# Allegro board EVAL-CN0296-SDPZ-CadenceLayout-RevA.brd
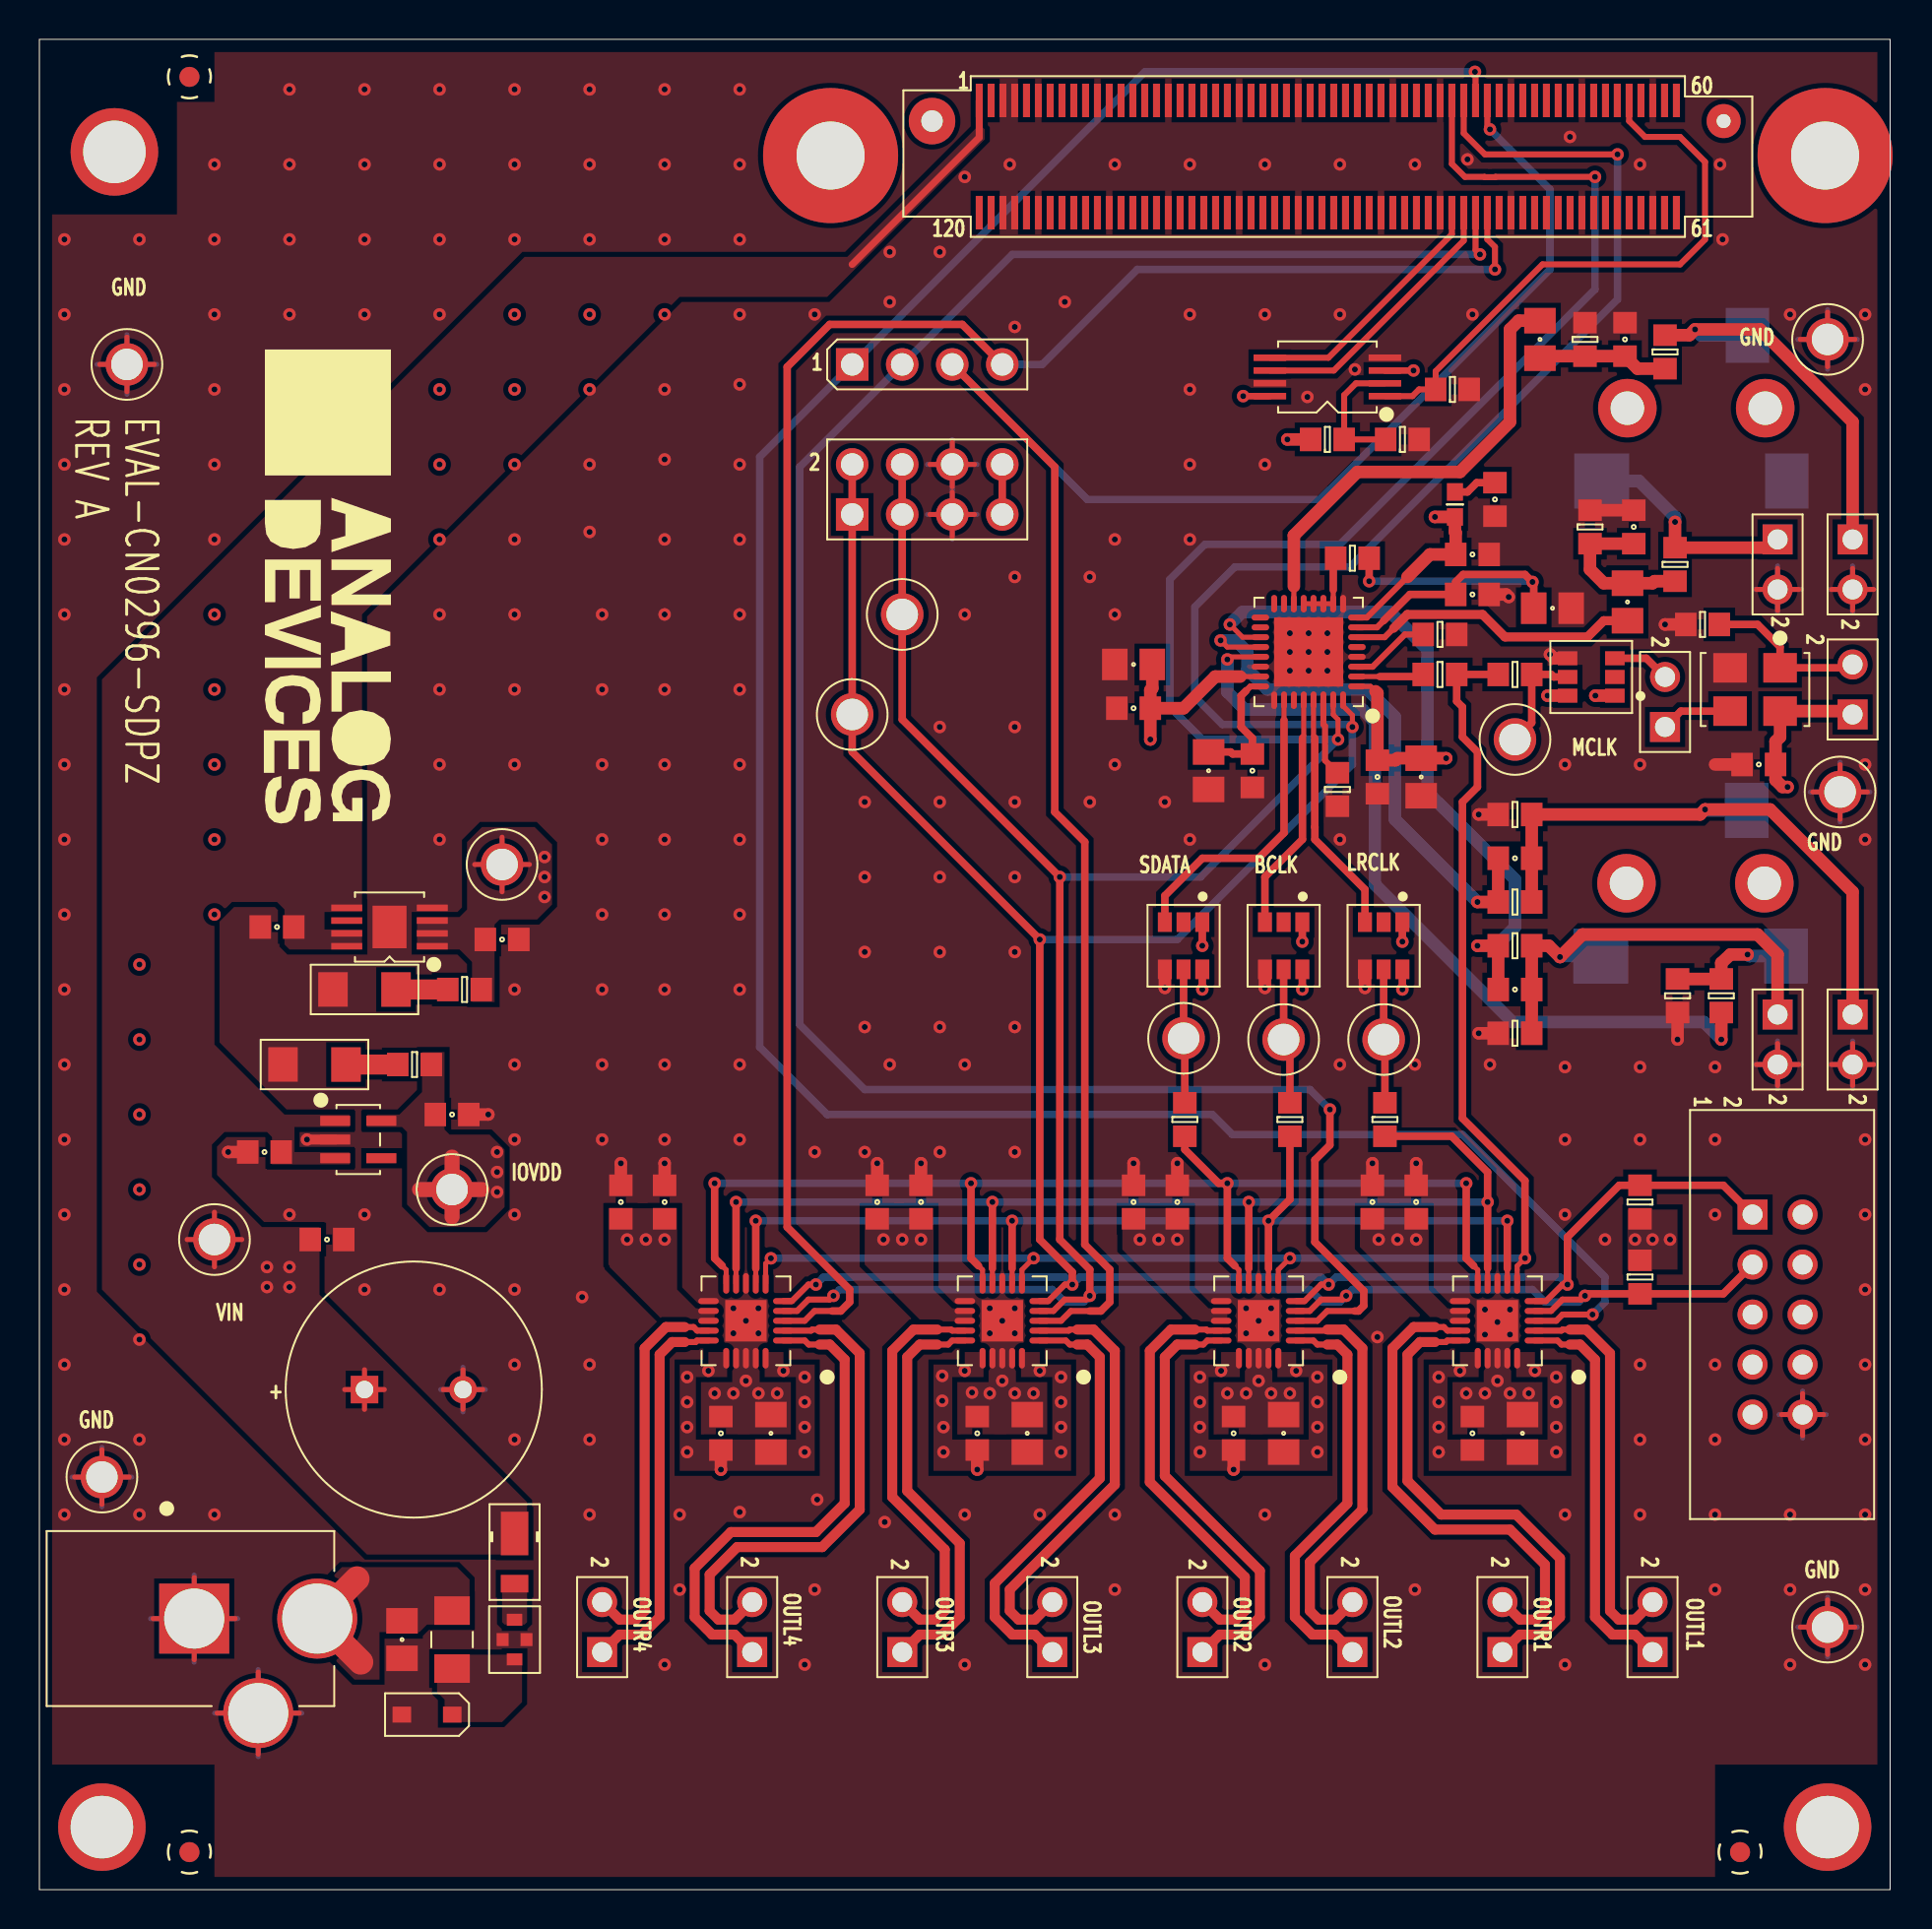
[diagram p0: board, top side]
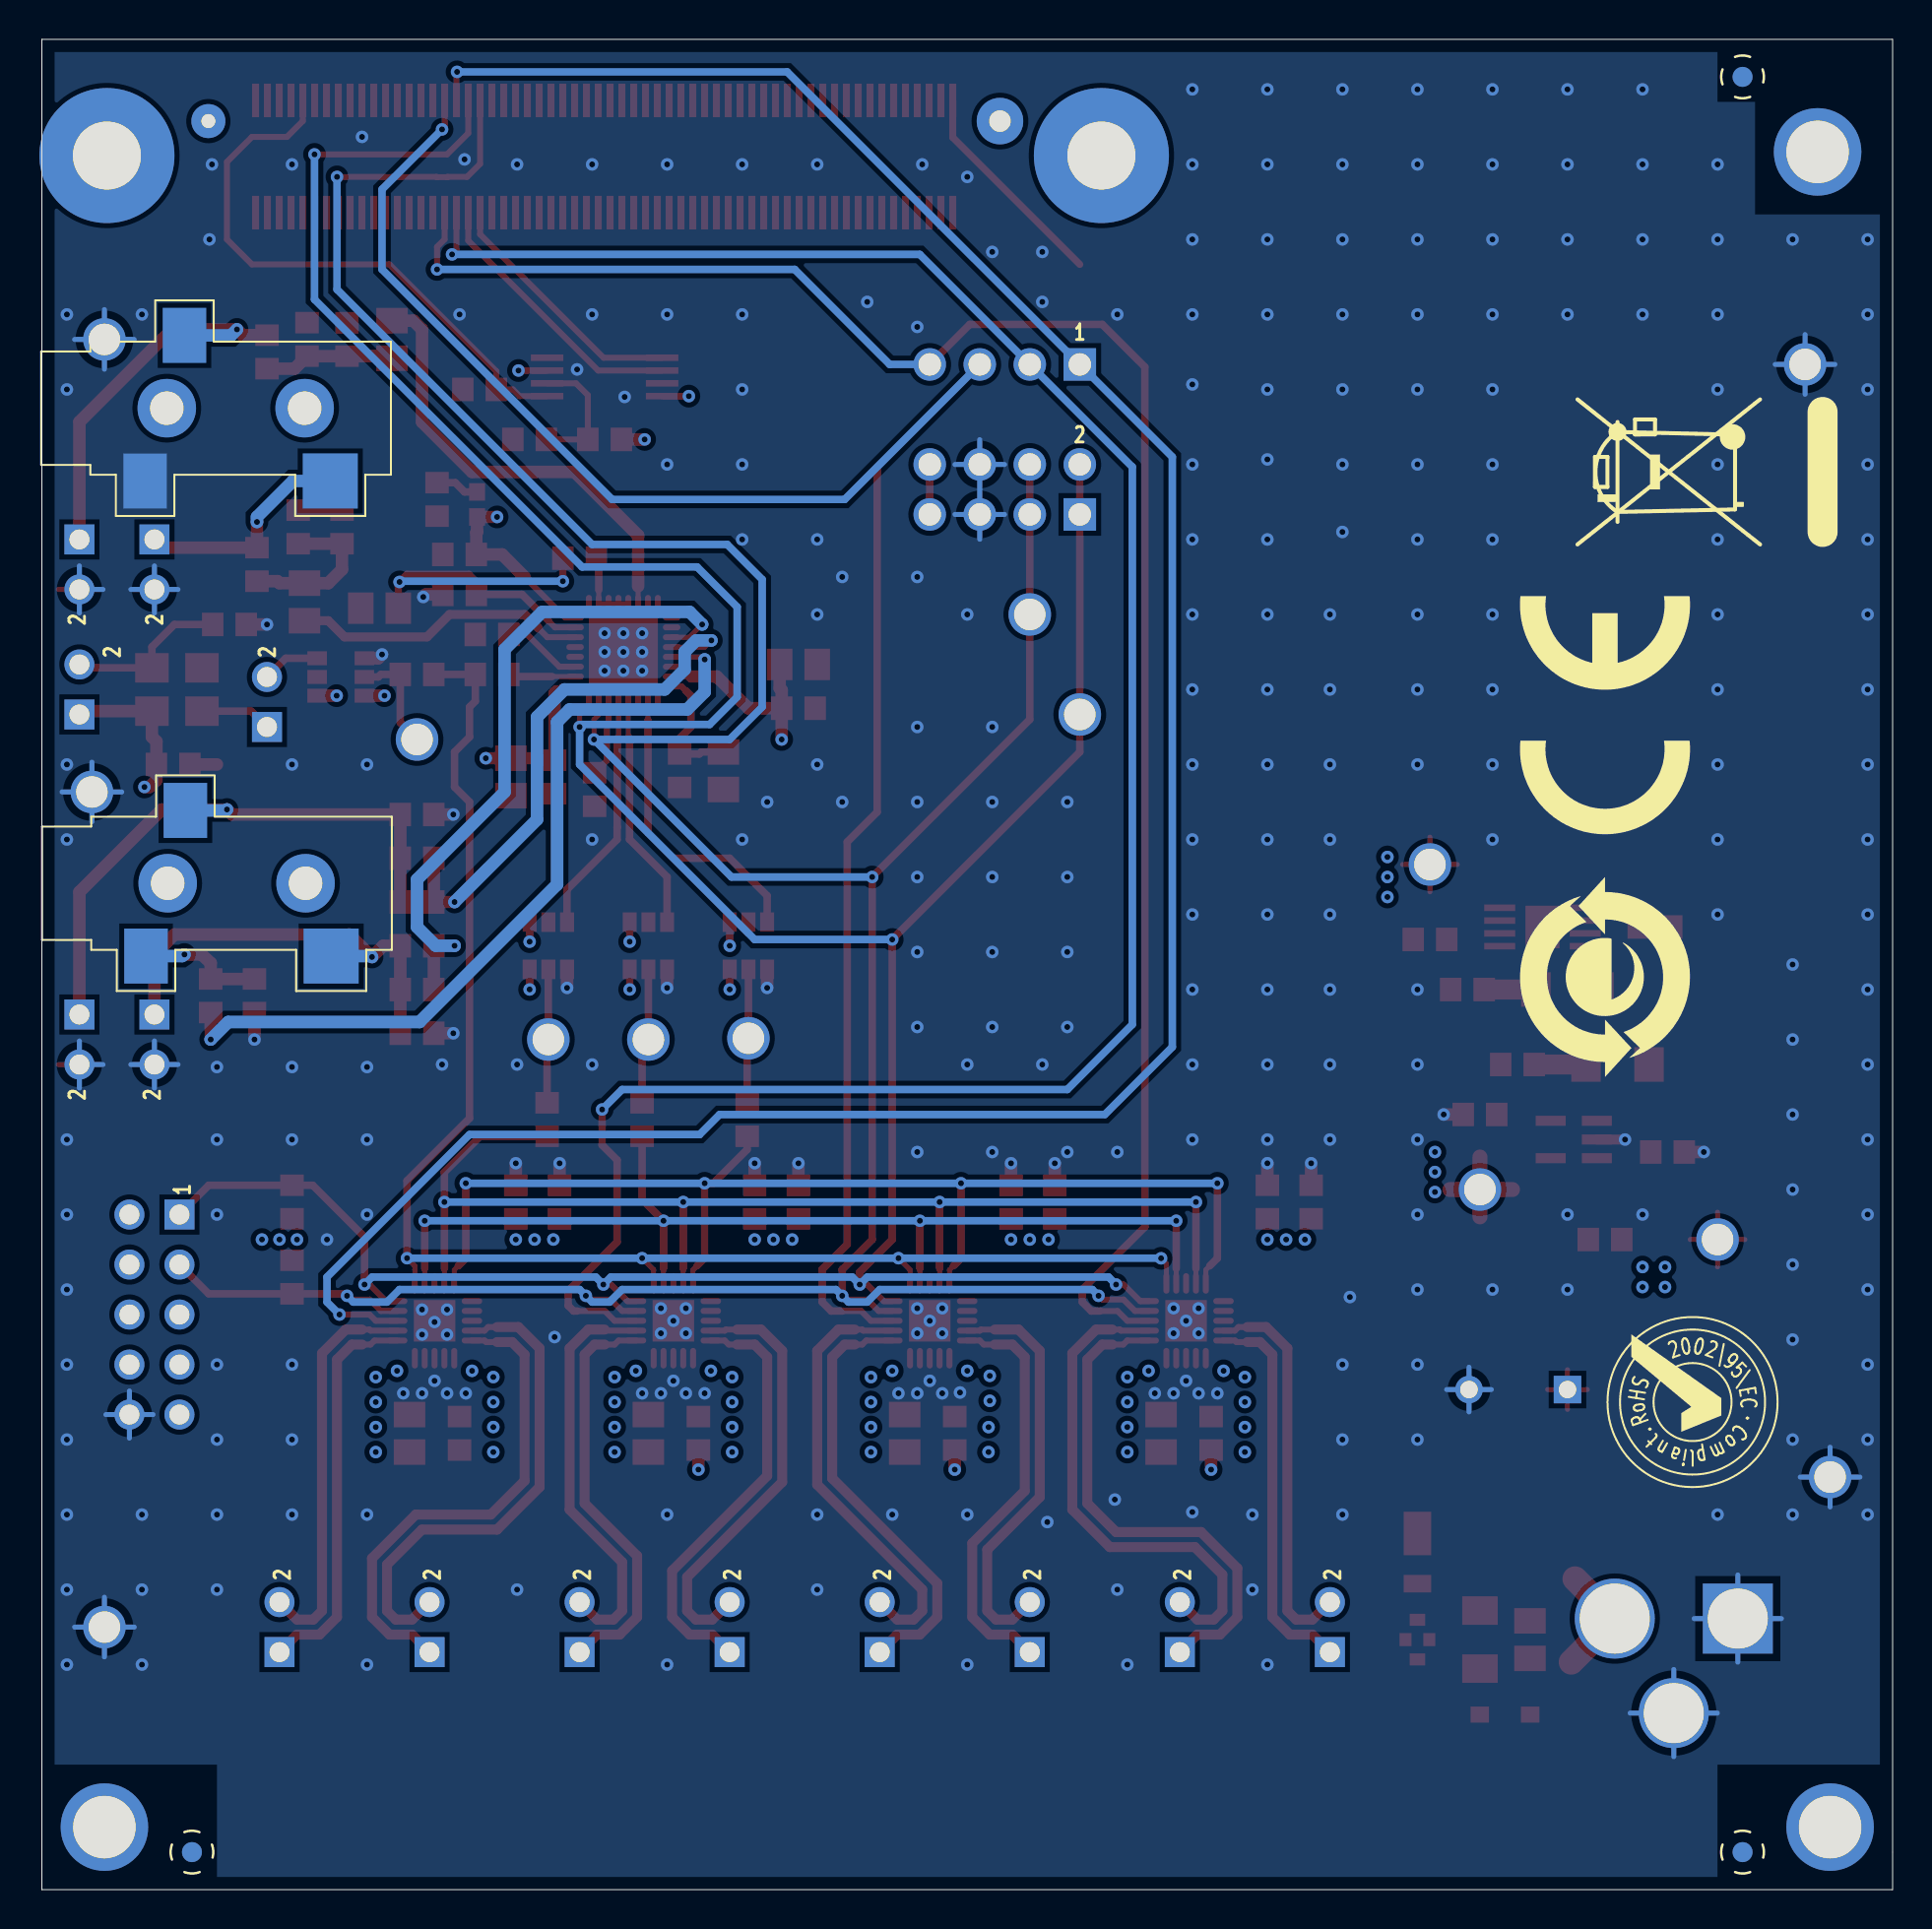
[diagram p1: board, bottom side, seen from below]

Outline 93.98 x 93.98 mm; copper layers: TOP, L2_DGND, L3_PWR, BOTTOM. Coordinates in mm from the lower left corner of the outline.
Outline path: 0,93.98 0,0 93.98,0 93.98,93.98 0,93.98

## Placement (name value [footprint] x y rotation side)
C1  1UF  [C0603]  11.43 37.47 180 top
C2  1.5uF  [C0603]  20.96 39.37 0 top
C3  4.7UF  [C0805]  18.41 12.7 270 top
C4  0.1uF  [C0603]  14.61 33.02 0 top
C5  1UF  [C0603]  12.07 48.9 180 top
C6  1.5uF  [C0603]  23.5 48.26 0 top
C7  1UF  [C0603]  29.53 34.93 90 top
C8  470uF  [CPLRAD197D492H866LD24]  16.51 25.4 0 top
C9  10UF  [C0603]  31.75 34.93 90 top
C10  0.1UF  [C0603]  34.61 23.18 270 top
C11  10UF  [C0805]  37.15 23.18 90 top
C12  10UF  [C0805]  55.56 62.23 0 top
C13  0.1uF  [C0603]  55.56 60.01 0 top
C14  0.1uF  [C0603]  72.77 67.82 180 top
C15  9.1pF  [C0603]  73.91 70.61 90 top
C16  10UF  [C0805]  59.37 56.83 270 top
C17  0.1uF  [C0603]  61.59 56.83 270 top
C18  10UF  [C0805]  70.17 56.52 270 top
C19  0.1uF  [C0603]  67.95 56.52 270 top
C20  10UF  [C0805]  76.84 65.09 0 top
C21  0.1uF  [C0603]  72.77 65.79 180 top
C22  10UF  [C0805]  80.65 65.41 270 top
C23  TBD0603  [C0603]  80.96 69.22 270 top
C24  10UF  [C0805]  76.2 78.74 90 top
C25  TBD0603  [C0603]  80.52 78.74 270 top
C26  TBD0603  [C0603]  74.93 52.39 180 top
C27  TBD0603  [C0603]  74.93 45.72 180 top
C28  0.01UF  [C0603]  87.31 57.15 180 top
C29  1UF  [C0603]  67.69 34.93 90 top
C30  10UF  [C0603]  69.91 34.93 90 top
C31  0.1UF  [C0603]  72.77 23.18 270 top
C32  10UF  [C0805]  75.31 23.18 90 top
C33  1UF  [C0603]  55.56 34.93 90 top
C34  10UF  [C0603]  57.78 34.93 90 top
C35  0.1UF  [C0603]  60.64 23.18 270 top
C36  10UF  [C0805]  63.18 23.18 90 top
C37  1UF  [C0603]  42.54 34.93 90 top
C38  10UF  [C0603]  44.77 34.93 90 top
C39  0.1UF  [C0603]  47.62 23.18 270 top
C40  10UF  [C0805]  50.16 23.18 90 top
D1  SML-LX1206IW-TR (red)  [LEDSML126W63H43]  13.97 41.91 0 top
D2  SML-LX1206IW-TR (red)  [LEDSML126W63H43]  16.51 45.72 0 top
D3  MMSZ5232BS-7  [SOD323-2]  19.68 8.89 180 top
D4  SBR2U30P1-7  [POWERDI123]  24.13 17.14 270 top
F1  5A  [F1206H46]  20.96 12.7 270 top
FR1  1uF  [C0805-4P]  24.13 12.7 90 top
J1  RAPC722X  [CNSWITCHRAPC722]  7.73 13.77 270 top
J2  SJ-3523-SMT  [CNCUISJ-3523-SMT]  84.14 75.25 180 bottom
J3  SJ-3523-SMT  [CNCUISJ-3523-SMT]  84.09 51.12 180 bottom
L1  1.2NH  [L0402]  71.88 70.36 270 top
NOREF  -  []  93.98 0 90 top
NOREF#2  -  []  93.34 0 90 top
NOREF#3  -  [unnamed#2]  7.62 1.91 0 top
NOREF#4  -  []  -240.03 -83.57 0 top
NOREF#5  -  [unnamed#2]  90.81 3.17 0 top
NOREF#6  -  []  93.98 0 0 top
NOREF#7  -  [unnamed#2]  3.17 3.17 0 top
NOREF#8  -  [unnamed#2]  86.36 1.91 0 top
NOREF#9  -  []  117.48 383.79 0 top
NOREF#10  -  [unnamed#2]  7.62 92.08 0 top
NOREF#11  -  []  -188.59 376.24 0 top
NOREF#12  -  []  -0.64 0 0 top
NOREF#13  -  []  -247.65 -92.71 0 top
NOREF#14  -  []  -248.92 -93.98 0 top
NOREF#15  -  []  93.98 93.98 180 top
NOREF#16  -  []  0 0 0 top
NOREF#17  -  []  14.61 65.53 270 top
NOREF#18  -  []  7.62 1.91 0 top
NOREF#19  -  []  0 93.98 270 top
NOREF#20  -  [unnamed#2]  3.81 88.27 0 top
NOREF#21  -  []  47.24 116.97 0 top
NOREF#22  -  []  0 0 0 top
NOREF#23  -  []  0 93.98 0 top
NOREF#24  -  []  -189.99 364.11 0 top
NOREF#25  -  []  7.62 1.91 0 top
NOREF#26  -  []  0 93.98 0 top
NOREF#27  -  []  14.61 46.36 90 bottom
NOREF#28  -  [unnamed#2]  86.36 1.91 180 bottom
NOREF#29  -  [unnamed#2]  7.62 92.08 180 bottom
NOREF#30  -  []  14.61 61.59 90 bottom
NOREF#31  -  []  19.68 81.28 90 bottom
NOREF#32  -  [unnamed#2]  7.62 1.91 180 bottom
NOREF#33  -  []  10.16 24.77 90 bottom
P1  FX8-120S-SV(21)  [CNHRSFX8-120S-SV_A]  65.43 88.03 0 top
P2  TSW-104-08-G-D  [CNSAMTEC2X4H330LD36]  41.27 69.85 0 top
P3  69157-102HLF  [CNBERG69157-102]  81.92 12.06 90 top
P4  69157-102HLF  [CNBERG69157-102]  66.67 12.06 90 top
P5  69157-102HLF  [CNBERG69157-102]  59.05 12.06 90 top
P6  69157-102HLF  [CNBERG69157-102]  92.08 59.69 90 top
P7  69157-102HLF  [CNBERG69157-102]  88.27 68.58 270 top
P8  69157-102HLF  [CNBERG69157-102]  92.08 68.58 270 top
P9  69157-102HLF  [CNBERG69157-102]  88.27 44.45 270 top
P10  69157-102HLF  [CNBERG69157-102]  92.08 44.45 270 top
P11  69157-102HLF  [CNBERG69157-102]  82.55 59.05 90 top
P12  69157-102HLF  [CNBERG69157-102]  51.43 12.06 90 top
P13  69157-102HLF  [CNBERG69157-102]  74.3 12.06 90 top
P14  3MN2510-6002RB  [CN3MN2510-6002RB]  87 34.29 270 top
P15  69157-102HLF  [CNBERG69157-102]  43.81 12.06 90 top
P16  69157-102HLF  [CNBERG69157-102]  36.2 12.06 90 top
P17  69157-102HLF  [CNBERG69157-102]  28.57 12.06 90 top
P18  TSW-104-08-G-S  [CNBERG1X4H205LD36]  41.27 77.47 0 top
R1  100K  [R0603]  65.41 73.66 0 top
R2  100K  [R0603]  71.76 76.2 0 top
R3  100K  [R0603]  69.22 73.66 0 top
R4  500  [R0603]  21.59 45.72 180 top
R5  0  [R0603]  71.12 63.75 180 top
R6  0  [R0603]  65.91 55.88 90 top
R7  4.7K  [R0603]  81.28 34.93 90 top
R8  4.7K  [R0603]  81.28 31.12 270 top
R9  500  [R0603]  19.05 41.91 180 top
R10  49.9  [R0603]  71.12 61.72 180 top
R11  1K  [R0603]  83.06 67.31 270 top
R12  49.9K  [R0603]  78.74 69.22 270 top
R13  1K  [R0603]  82.55 78.11 270 top
R14  49.9K  [R0603]  78.49 78.74 270 top
R15  0  [R0603]  66.67 67.63 0 top
R16  0  [R0603]  74.93 50.16 0 top
R17  0  [R0603]  74.93 47.94 0 top
R18  0  [R0603]  85.41 45.4 90 top
R19  TBD0603  [R0603]  83.19 45.4 90 top
R20  TBD0603  [R0603]  74.93 43.5 0 top
R21  TBD0603  [R0603]  74.93 54.61 0 top
R22  10K  [R0603]  84.45 64.26 0 top
R23  33  [R0603]  74.93 61.72 180 top
R24  33  [R0603]  58.17 39.12 270 top
R25  33  [R0603]  68.33 39.12 270 top
R26  33  [R0603]  63.5 39.12 270 top
TP1  BLK  [CNLOOPTP]  3.17 20.96 90 top
TP2  BLK  [CNLOOPTP]  90.81 13.33 90 top
TP3  RED  [CNLOOPTP]  20.96 35.56 270 top
TP4  RED  [CNLOOPTP]  8.89 33.02 0 top
TP5  RED  [CNLOOPTP]  23.5 52.07 90 top
TP6  WHT  [CNLOOPTP]  58.1 43.24 180 top
TP7  WHT  [CNLOOPTP]  68.26 43.18 180 top
TP8  WHT  [CNLOOPTP]  63.18 43.18 180 top
TP9  WHT  [CNLOOPTP]  74.93 58.42 180 top
TP10  BLK  [CNLOOPTP]  91.44 55.75 0 top
TP11  BLK  [CNLOOPTP]  4.45 77.47 0 top
TP12  BLK  [CNLOOPTP]  90.81 78.74 0 top
TP13  WHT  [CNLOOPTP]  41.27 59.69 0 top
TP14  WHT  [CNLOOPTP]  43.81 64.77 0 top
U1  ADP121-AUJZ33R7  [TSOT-5]  16.19 38.1 270 top
U2  24LC32A-I/ST  [TSSOP8]  65.41 76.84 90 top
U3  ADP124ARHZ-3.3-R7  [MSOP8_PAD2_16X1_73]  17.78 48.9 90 top
U4  SSM2518BCPZ  [QFN20_4X4_PAD2_1X2_1]  35.88 28.89 90 top
U5  ADAU1761BCPZ  [QFN32_5X5_PAD3_5X3_5]  64.45 62.87 90 top
U6  ADG3231BRJZ  [SOT23_6-2]  58.1 47.94 180 top
U7  ADG3231BRJZ  [SOT23_6-2]  68.26 47.94 180 top
U8  ADG3231BRJZ  [SOT23_6-2]  63.18 47.94 180 top
U9  ADG3231BRJZ  [SOT23_6-2]  78.8 61.59 90 top
U10  SSM2518BCPZ  [QFN20_4X4_PAD2_1X2_1]  74.04 28.89 90 top
U11  SSM2518BCPZ  [QFN20_4X4_PAD2_1X2_1]  61.91 28.89 90 top
U12  SSM2518BCPZ  [QFN20_4X4_PAD2_1X2_1]  48.89 28.89 90 top
Y1  12.288MEGHz  [YSML197W126H51_A]  87.12 60.96 180 top

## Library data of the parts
C1 C5 C7 C29 C33 C37 = CAP: Tolerance: 10; User Part Number: UPN; alternate symbols: (C0402H22_ALT,C0201-2); part number: CAP_SM-1UF,16V,10,E006882,C0603; tolerance: 10
C2 C6 = CAP: Tolerance: 10; User Part Number: UPN; alternate symbols: (C0402H22_ALT,C0201-2); part number: CAP_SM-1.5UF,25V,10,E014229,C0603; tolerance: 10
C3 = CAP: Tolerance: 10; User Part Number: UPN; alternate symbols: (C0402H22_ALT,C0201-2); part number: CAP_SM-4.7UF,25V,10,E006908,C0805; tolerance: 10
C4 = CAP: Tolerance: 10; User Part Number: UPN; alternate symbols: (C0402H22_ALT,C0201-2); part number: CAP_SM-0.1UF,16V,10,E015036,C0603; tolerance: 10
C8 = CAPP: User Part Number: UPN; Tolerance: 20; part number: CAPP_TH-470UF,63V,20,E016987,CPLRAD197D492H866LD24; tolerance: 20
C9 C30 C34 C38 = CAP: Tolerance: 20; User Part Number: UPN; alternate symbols: (C0402H22_ALT,C0201-2); part number: CAP_SM-10UF,6.3V,20,E007143,C0603; tolerance: 20
C10 C31 C35 C39 = CAP: Tolerance: 10; User Part Number: UPN; alternate symbols: (C0402H22_ALT,C0201-2); part number: CAP_SM-0.1UF,25V,10,E007204,C0603; tolerance: 10
C11 C12 C16 C18 C20 C22 C24 C32 C36 C40 = CAP: Tolerance: 10; User Part Number: UPN; alternate symbols: (C0402H22_ALT,C0201-2); part number: CAP_SM-10UF,16V,10,E006166,C0805; tolerance: 10
C13 C14 C17 C19 C21 = CAP: Tolerance: 10; User Part Number: UPN; alternate symbols: (C0402H22_ALT,C0201-2); part number: CAP_SM-0.1UF,50V,10,E015248,C0603; tolerance: 10
C15 = CAP: Tolerance: +/-0.5PF; User Part Number: UPN; alternate symbols: (C0402H22_ALT,C0201-2); part number: CAP_SM-9.1PF,50V,+/-0.5PF,E016007,C0603; tolerance: +/-0.5PF
C23 C25-C27 = CAP: User Part Number: UPN; alternate symbols: (C0402H22_ALT,C0201-2); part number: CAP_SM-TBD0603,TBD0603,TBD0603,E000382,C0603
C28 = CAP: Tolerance: 10; User Part Number: UPN; alternate symbols: (C0402H22_ALT,C0201-2); part number: CAP_SM-0.01UF,50V,10,E000421,C0603; tolerance: 10
D1 D2 = DIOLED: Tolerance: N/A; User Part Number: UPN; part number: DIOLED_SM-SML-LX1206IW-TR (RED),2.0V,N/A,E008005,LEDSML126W63H43; tolerance: N/A
D3 = DIOZNR: Tolerance: N/A; User Part Number: UPN; part number: DIOZNR_SM-MMSZ5232BS-7,5.6V,N/A,E001255,SOD323-2; tolerance: N/A
D4 = DIO: User Part Number: UPN; Tolerance: N/A; part number: DIO_SM-SBR2U30P1-7,30V,N/A,E016912,POWERDI123; tolerance: N/A
F1 = FSFUSE: User Part Number: UPN; part number: FSFUSE_SM-5A,32V,E016049,F1206H46
FR1 = CAP4P_V3: Tolerance: 20; User Part Number: UPN; part number: CAP4P_V3_SM-1UF,16V,20,E014204,C0805-4P; tolerance: 20
J1 = CN3P_RAPC722: User Part Number: UPN; part number: CN3P_RAPC722_TH-RAPC722X,E006713,CNSWITCHRAPC722
J2 J3 = CN3P: User Part Number: UPN; part number: CN3P_SM-SJ-3523-SMT,E008203,CNCUISJ-3523-SMT
L1 = IND: Tolerance: N/A; User Part Number: UPN; alternate symbols: (L0402-2,L0603_ALT); part number: IND_SM-1.2NH,N/A,E002399,L0402; tolerance: N/A
P1 = CN120P_V4: User Part Number: UPN; part number: CN120P_V4_SM-FX8-120S-SV(21),E016993,CNHRSFX8-120S-SV_A
P2 = CN8P_A: User Part Number: UPN; part number: CN8P_A_TH-TSW-104-08-G-D,E006589,CNSAMTEC2X4H330LD36
P3-P13 P15-P17 = CN2P: User Part Number: UPN; part number: CN2P_TH-69157-102HLF,E017268,CNBERG69157-102
P14 = CN10P: User Part Number: UPN; part number: CN10P_TH-3MN2510-6002RB,E005954,CN3MN2510-6002RB
P18 = CN4P: User Part Number: UPN; part number: CN4P_TH-TSW-104-08-G-S,E000828,CNBERG1X4H205LD36
R1-R3 = RES: Tolerance: 1; User Part Number: UPN; alternate symbols: (RRAD984L1500W75H520LD32); part number: RES_SM-100K,1/10W,1,E010279,R0603; tolerance: 1
R4 R9 = RES: Tolerance: 1; User Part Number: UPN; alternate symbols: (RRAD984L1500W75H520LD32); part number: RES_SM-500,1/10W,1,E012854,R0603; tolerance: 1
R5 R6 R15-R18 = RES: Tolerance: 5; User Part Number: UPN; alternate symbols: (RRAD984L1500W75H520LD32); part number: RES_SM-0,1/10W,5,E006826,R0603; tolerance: 5
R7 R8 = RES: Tolerance: 1; User Part Number: UPN; alternate symbols: (RRAD984L1500W75H520LD32); part number: RES_SM-4.7K,1/10W,1,E010097,R0603; tolerance: 1
R10 = RES: Tolerance: 1; User Part Number: UPN; alternate symbols: (RRAD984L1500W75H520LD32); part number: RES_SM-49.9,1/10W,1,E003673,R0603; tolerance: 1
R11 R13 = RES: Tolerance: 1; User Part Number: UPN; alternate symbols: (RRAD984L1500W75H520LD32); part number: RES_SM-1K,1/10W,1,E003678,R0603; tolerance: 1
R12 R14 = RES: Tolerance: 1; User Part Number: UPN; alternate symbols: (RRAD984L1500W75H520LD32); part number: RES_SM-49.9K,1/10W,1,E015342,R0603; tolerance: 1
R19-R21 = RES: User Part Number: UPN; alternate symbols: (RRAD984L1500W75H520LD32); part number: RES_SM-TBD0603,TBD0603,TBD0603,E004050,R0603
R22 = RES: Tolerance: 1; User Part Number: UPN; alternate symbols: (RRAD984L1500W75H520LD32); part number: RES_SM-10K,1/10W,1,E003671,R0603; tolerance: 1
R23-R26 = RES: Tolerance: 1; User Part Number: UPN; alternate symbols: (RRAD984L1500W75H520LD32); part number: RES_SM-33,1/16W,1,E004232,R0603; tolerance: 1
TP1 TP2 TP10-TP12 = CNTP1P: User Part Number: UPN; part number: CNTP1P_TH-BLK,E000948,CNLOOPTP
TP3-TP5 = CNTP1P: User Part Number: UPN; part number: CNTP1P_TH-RED,E000947,CNLOOPTP
TP6-TP9 TP13 TP14 = CNTP1P: User Part Number: UPN; part number: CNTP1P_TH-WHT,E000946,CNLOOPTP
U1 = ADP121: User Part Number: UPN; part number: ADP121_SM-ADP121-AUJZ33R7,E013943,TSOT-5,N/A
U2 = IC24FC256: User Part Number: UPN; part number: IC24FC256_SM-24LC32A-I/ST,E014553,TSSOP8
U3 = ADP124: User Part Number: UPN; part number: ADP124_SM-ADP124ARHZ-3.3-R7,E012626,MSOP8_PAD2_16X1_73,N/A
U4 U10-U12 = SSM2518_PRELIM: User Part Number: UPN; part number: SSM2518_PRELIM_SM-SSM2518BCPZ,E011776,QFN20_4X4_PAD2_1X2_1,N/A
U5 = ADAU1761: User Part Number: UPN; part number: ADAU1761_SM-ADAU1761BCPZ,E015703,QFN32_5X5_PAD3_5X3_5,N/A
U6-U9 = ADG3231: User Part Number: UPN; part number: ADG3231_SM-ADG3231BRJZ,E013463,SOT23_6-2,N/A
Y1 = XTALOSC4P_V2: User Part Number: UPN; part number: XTALOSC4P_V2_SM-12.288MEGHZ,E016278,YSML197W126H51_A

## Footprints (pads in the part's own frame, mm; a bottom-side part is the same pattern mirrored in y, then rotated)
C0603
  rect 1.092x1.194 smd: 1(-0.851,0) 2(0.851,0)
C0805
  rect 1.295x1.6 smd: 1(-0.953,0) 2(0.953,0)
C0805-4P
  rect 0.61x0.787 smd: 1(-1.006,0) 3(1.006,0)
  rect 0.66x0.61 smd: G1(0,-0.605) G2(0,0.605)
CN3MN2510-6002RB
  rect 1.524x1.524 hole 1.016: 1(0,0)
  round 1.524 hole 1.016: 2(0,2.54) 3(2.54,0) 4(2.54,2.54) 5(5.08,0) 6(5.08,2.54) 7(7.62,0) 8(7.62,2.54) 9(10.16,0) 10(10.16,2.54)
CNBERG1X4H205LD36
  rect 1.651x1.651 hole 1.143: 1(0,0)
  round 1.651 hole 1.143: 2(2.54,0) 3(5.08,0) 4(7.62,0)
CNBERG69157-102
  rect 1.524x1.524 hole 1.016: 1(0,0)
  round 1.524 hole 1.016: 2(2.54,0)
CNCUISJ-3523-SMT
  round 2.972 hole 1.702 unplated: (-3.5,0) (3.5,0)
  rect 2.21x2.794 smd: 1(-4.6,-3.698) 3(-2.601,3.698)
  rect 2.794x2.794 smd: 2(4.801,-3.698)
CNHRSFX8-120S-SV_A
  round 6.858 hole 3.454 unplated: (-25.25,0.051) (25.25,0.051)
  round 2.362 hole 1.092 unplated: (-20.099,1.801)
  round 1.727 hole 0.711 unplated: (20.099,1.801)
  rect 0.356x1.702 smd: 1(-17.701,2.85) 2(-17.099,2.85) 3(-16.5,2.85) 4(-15.9,2.85) 5(-15.301,2.85) 6(-14.699,2.85) 7(-14.1,2.85) 8(-13.5,2.85) 9(-12.901,2.85) 10(-12.301,2.85) 11(-11.699,2.85) 12(-11.1,2.85) 13(-10.5,2.85) 14(-9.901,2.85) 15(-9.299,2.85) 16(-8.7,2.85) 17(-8.1,2.85) 18(-7.501,2.85) 19(-6.901,2.85) 20(-6.299,2.85) 21(-5.7,2.85) 22(-5.1,2.85) 23(-4.501,2.85) 24(-3.899,2.85) 25(-3.299,2.85) 26(-2.7,2.85) 27(-2.101,2.85) 28(-1.501,2.85) 29(-0.899,2.85) 30(-0.3,2.85) 31(0.3,2.85) 32(0.899,2.85) 33(1.501,2.85) 34(2.101,2.85) 35(2.7,2.85) 36(3.299,2.85) 37(3.899,2.85) 38(4.501,2.85) 39(5.1,2.85) 40(5.7,2.85) 41(6.299,2.85) 42(6.901,2.85) 43(7.501,2.85) 44(8.1,2.85) 45(8.7,2.85) 46(9.299,2.85) 47(9.901,2.85) 48(10.5,2.85) 49(11.1,2.85) 50(11.699,2.85) 51(12.301,2.85) 52(12.901,2.85) 53(13.5,2.85) 54(14.1,2.85) 55(14.699,2.85) 56(15.301,2.85) 57(15.9,2.85) 58(16.5,2.85) 59(17.099,2.85) 60(17.701,2.85) 61(17.701,-2.85) 62(17.099,-2.85) 63(16.5,-2.85) 64(15.9,-2.85) 65(15.301,-2.85) 66(14.699,-2.85) 67(14.1,-2.85) 68(13.5,-2.85) 69(12.901,-2.85) 70(12.301,-2.85) 71(11.699,-2.85) 72(11.1,-2.85) 73(10.5,-2.85) 74(9.901,-2.85) 75(9.299,-2.85) 76(8.7,-2.85) 77(8.1,-2.85) 78(7.501,-2.85) 79(6.901,-2.85) 80(6.299,-2.85) 81(5.7,-2.85) 82(5.1,-2.85) 83(4.501,-2.85) 84(3.899,-2.85) 85(3.299,-2.85) 86(2.7,-2.85) 87(2.101,-2.85) 88(1.501,-2.85) 89(0.899,-2.85) 90(0.3,-2.85) 91(-0.3,-2.85) 92(-0.899,-2.85) 93(-1.501,-2.85) 94(-2.101,-2.85) 95(-2.7,-2.85) 96(-3.299,-2.85) 97(-3.899,-2.85) 98(-4.501,-2.85) 99(-5.1,-2.85) 100(-5.7,-2.85) 101(-6.299,-2.85) 102(-6.901,-2.85) 103(-7.501,-2.85) 104(-8.1,-2.85) 105(-8.7,-2.85) 106(-9.299,-2.85) 107(-9.901,-2.85) 108(-10.5,-2.85) 109(-11.1,-2.85) 110(-11.699,-2.85) 111(-12.301,-2.85) 112(-12.901,-2.85) 113(-13.5,-2.85) 114(-14.1,-2.85) 115(-14.699,-2.85) 116(-15.301,-2.85) 117(-15.9,-2.85) 118(-16.5,-2.85) 119(-17.099,-2.85) 120(-17.701,-2.85)
CNLOOPTP
  round 2.159 hole 1.6: 1(0,0)
CNSAMTEC2X4H330LD36
  rect 1.651x1.651 hole 1.143: 1(0,0)
  round 1.651 hole 1.143: 2(0,2.54) 3(2.54,0) 4(2.54,2.54) 5(5.08,0) 6(5.08,2.54) 7(7.62,0) 8(7.62,2.54)
CNSWITCHRAPC722
  rect 3.556x3.556 hole 3.048: 1(0,0.127)
  round 3.556 hole 3.048: 2(4.801,3.378)
  round 4.064 hole 3.556: 3(0,6.375)
CPLRAD197D492H866LD24
  round 1.397 hole 0.889: N(5.001,0)
  rect 1.397x1.397 hole 0.889: P(0,0)
F1206H46
  rect 1.448x1.803 smd: 1(-1.473,0) 2(1.473,0)
L0402
  rect 0.889x0.813 smd: 1(-0.635,0) 2(0.635,0)
LEDSML126W63H43
  rect 1.499x1.753 smd: A(1.6,0) C(-1.6,0)
MSOP8_PAD2_16X1_73
  rect 0.33x1.575 smd: 1(-0.975,-2.172) 2(-0.325,-2.172) 3(0.325,-2.172) 4(0.975,-2.172) 5(0.975,2.172) 6(0.325,2.172) 7(-0.325,2.172) 8(-0.975,2.172)
  rect 2.159x1.727 smd: PAD(0,0)
POWERDI123
  rect 0.889x1.397 smd: A(1.605,0)
  rect 2.21x1.397 smd: C(-0.945,0)
QFN20_4X4_PAD2_1X2_1
  oval 0.305x1.041 smd: 1(-1.001,-1.9) 2(-0.5,-1.9) 3(0,-1.9) 4(0.5,-1.9) 5(1.001,-1.9) 11(1.001,1.9) 12(0.5,1.9) 13(0,1.9) 14(-0.5,1.9) 15(-1.001,1.9)
  oval 1.041x0.305 smd: 6(1.9,-1.001) 7(1.9,-0.5) 8(1.9,0) 9(1.9,0.5) 10(1.9,1.001) 16(-1.9,1.001) 17(-1.9,0.5) 18(-1.9,0) 19(-1.9,-0.5) 20(-1.9,-1.001)
  rect 2.108x2.108 smd: PAD(0,0)
QFN32_5X5_PAD3_5X3_5
  oval 0.305x0.889 smd: 1(-1.75,-2.451) 2(-1.25,-2.451) 3(-0.749,-2.451) 4(-0.249,-2.451) 5(0.249,-2.451) 6(0.749,-2.451) 7(1.25,-2.451) 8(1.75,-2.451) 17(1.75,2.451) 18(1.25,2.451) 19(0.749,2.451) 20(0.249,2.451) 21(-0.249,2.451) 22(-0.749,2.451) 23(-1.25,2.451) 24(-1.75,2.451)
  oval 0.889x0.305 smd: 9(2.451,-1.75) 10(2.451,-1.25) 11(2.451,-0.749) 12(2.451,-0.249) 13(2.451,0.249) 14(2.451,0.749) 15(2.451,1.25) 16(2.451,1.75) 25(-2.451,1.75) 26(-2.451,1.25) 27(-2.451,0.749) 28(-2.451,0.249) 29(-2.451,-0.249) 30(-2.451,-0.749) 31(-2.451,-1.25) 32(-2.451,-1.75)
  rect 3.505x3.505 smd: PAD(0,0)
R0603
  rect 1.092x1.194 smd: 1(-0.851,0) 2(0.851,0)
SOD323-2
  rect 0.94x0.813 smd: A(1.28,0) C(-1.28,0)
SOT23_6-2
  rect 0.711x0.991 smd: 1(-0.95,-1.199) 2(0,-1.199) 3(0.95,-1.199) 4(0.95,1.199) 5(0,1.199) 6(-0.95,1.199)
TSOT-5
  rect 0.508x1.524 smd: 1(-0.95,-1.171) 2(0,-1.171) 3(0.95,-1.171) 4(0.95,1.171) 5(-0.95,1.171)
TSSOP8
  rect 0.33x1.651 smd: 1(-0.975,-2.921) 2(-0.325,-2.921) 3(0.325,-2.921) 4(0.975,-2.921) 5(0.975,2.921) 6(0.325,2.921) 7(-0.325,2.921) 8(-0.975,2.921)
unnamed#2
  round 1.016 smd: (0,0)
YSML197W126H51_A
  rect 1.702x1.499 smd: 1(-1.27,-1.1) 2(1.27,-1.1) 3(1.27,1.1) 4(-1.27,1.1)

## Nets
AVDD: C6.1(N1) C12.2(N2) C13.2(N2) C14.2(N2) C28.1(N1) L1.2(N2) P6.1(N1) R4.1(N1) TP5.1(N1) U3.1(VOUT1) U3.2(VOUT2) U3.3(VOUT_SENSE) U5.8(AVDD1) U5.23(AVDD2) U6.1(VCC1) U7.1(VCC1) U8.1(VCC1) U9.1(VCC1) Y1.4(VDD)
DGND: C1.2(N2) C2.2(N2) C3.2(N2) C4.2(N2) C5.2(N2) C6.2(N2) C7.2(N2) C8.N(N2) C9.2(N2) C10.1(N1) C11.2(N2) C12.1(N1) C13.1(N1) C14.1(N1) C15.1(N1) C16.2(N2) C17.2(N2) C18.2(N2) C19.2(N2) C20.2(N2) C21.1(N1) C23.1(N1) C25.1(N1) C28.2(N2) C29.2(N2) C30.2(N2) C31.1(N1) C32.2(N2) C33.2(N2) C34.2(N2) C35.1(N1) C36.2(N2) C37.2(N2) C38.2(N2) C39.1(N1) C40.2(N2) D1.C(N) D2.C(N) D3.A(P) FR1.G1(GND1) FR1.G2(GND2) J1.1(SH1) J1.2(SH2) J2.1(N1) P1.3(GND1) P1.4(GND2) P1.6(GND3) P1.11(GND4) P1.17(GND5) P1.23(GND6) P1.28(GND7) P1.36(GND8) P1.40(GND9) P1.46(GND10) P1.52(GND11) P1.58(GND12) P1.63(GND13) P1.69(GND14) P1.75(GND15) P1.81(GND16) P1.86(GND17) P1.93(GND18) P1.98(GND19) P1.104(GND20) P1.109(GND21) P1.115(GND22) P1.117(GND23) P1.118(GND24) P2.5(N5) P2.6(N6) P7.2(N2) P8.2(N2) P9.2(N2) P10.2(N2) P14.10(N10) R2.2(N2) R3.2(N2) R5.1(N1) R6.1(N1) R12.1(N1) R14.1(N1) R19.1(N1) R20.1(N1) R21.1(N1) R22.1(N1) TP1.1(N1) TP2.1(N1) TP10.1(N1) TP11.1(N1) TP12.1(N1) U1.2(GND) U2.4(VSS) U2.7(WP) U3.4(GND) U3.PAD(EP) U4.8(GND_1) U4.11(SAMOD) U4.17(GND_2) U4.18(GND_3) U4.19(GND_4) U4.PAD U5.4(JACKDET/MICIN) U5.9(AGND1) U5.22(AGND2) U5.25(DGND) U5.PAD U6.4(GND) U7.4(GND) U8.4(GND) U9.4(GND) U10.8(GND_1) U10.11(SAMOD) U10.17(GND_2) U10.18(GND_3) U10.19(GND_4) U10.PAD U11.8(GND_1) U11.11(SAMOD) U11.17(GND_2) U11.18(GND_3) U11.19(GND_4) U11.PAD U12.8(GND_1) U12.11(SAMOD) U12.17(GND_2) U12.18(GND_3) U12.19(GND_4) U12.PAD Y1.2(GND)
VIN: C1.1(N1) C4.1(N1) C5.1(N1) C8.P(N1) C10.2(N2) C11.1(N1) C31.2(N2) C32.1(N1) C35.2(N2) C36.1(N1) C39.2(N2) C40.1(N1) D4.C(N) P1.1(VIN) TP4.1(N1) U1.1(IN) U1.3(EN) U3.5(EN) U3.7(VIN1) U3.8(VIN2) U4.16(PVDD_1) U4.20(PVDD_2) U10.16(PVDD_1) U10.20(PVDD_2) U11.16(PVDD_1) U11.20(PVDD_2) U12.16(PVDD_1) U12.20(PVDD_2)
ADC_SDATA: U5.26(ADC_SDATA/GPIO1) U6.3(A)
ADDR_1: P1.43(GPIO0) P18.1(N1) U10.3(ADDR)
ADDR_2: P1.78(GPIO1) P18.2(N2) U11.3(ADDR)
ADDR_3: P1.44(GPIO2) P18.3(N3) U12.3(ADDR)
ADDR_4: P1.77(GPIO3) P18.4(N4) U4.3(ADDR)
BCLK: R26.2(N2) U4.7(BCLK) U10.7(BCLK) U11.7(BCLK) U12.7(BCLK)
BCLK_0: U5.28(BCLK/GPIO2) U8.3(A)
IOVDD: C2.1(N1) C7.1(N1) C9.1(N1) C18.1(N1) C19.1(N1) C29.1(N1) C30.1(N1) C33.1(N1) C34.1(N1) C37.1(N1) C38.1(N1) R1.1(N1) R7.1(N1) R8.1(N1) R9.1(N1) TP3.1(N1) U1.5(OUT) U2.3(A2) U2.8(VCC) U4.12(DVDD) U4.13(SD_N) U5.1(IOVDD) U6.6(VCC2) U7.6(VCC2) U8.6(VCC2) U9.6(VCC2) U10.12(DVDD) U10.13(SD_N) U11.12(DVDD) U11.13(SD_N) U12.12(DVDD) U12.13(SD_N)
LRCLK: R25.2(N2) U4.9(LRCLK) U10.9(LRCLK) U11.9(LRCLK) U12.9(LRCLK)
LRCLK_0: U5.29(LRCLK/GPIO3) U7.3(A)
MCLK: R10.1(N1) R23.2(N2) U4.6(MCLK) U10.6(MCLK) U11.6(MCLK) U12.6(MCLK)
MCLK_0: P11.2(N2) U9.3(A)
OUTL+_1: P3.1(N1) U10.1(OUTL_POS)
OUTL+_2: P4.1(N1) U11.1(OUTL_POS)
OUTL+_3: P12.1(N1) U12.1(OUTL_POS)
OUTL+_4: P16.1(N1) U4.1(OUTL_POS)
OUTL-_1: P3.2(N2) U10.2(OUTL_NEG)
OUTL-_2: P4.2(N2) U11.2(OUTL_NEG)
OUTL-_3: P12.2(N2) U12.2(OUTL_NEG)
OUTL-_4: P16.2(N2) U4.2(OUTL_NEG)
OUTR+_1: P13.1(N1) U10.15(OUTR_POS)
OUTR+_2: P5.1(N1) U11.15(OUTR_POS)
OUTR+_3: P15.1(N1) U12.15(OUTR_POS)
OUTR+_4: P17.1(N1) U4.15(OUTR_POS)
OUTR-_1: P13.2(N2) U10.14(OUTR_NEG)
OUTR-_2: P5.2(N2) U11.14(OUTR_NEG)
OUTR-_3: P15.2(N2) U12.14(OUTR_NEG)
OUTR-_4: P17.2(N2) U4.14(OUTR_NEG)
SCL: P1.42(SCL_1) P2.1(N1) P2.2(N2) P14.1(N1) R7.2(N2) TP13.1(N1) U4.5(SCK) U5.32(SCL/CCLK) U10.5(SCK) U11.5(SCK) U12.5(SCK)
SDA: P1.41(SDA_1) P2.3(N3) P2.4(N4) P14.3(N3) R8.2(N2) TP14.1(N1) U4.4(SDA) U5.31(SDA/COUT) U10.4(SDA) U11.4(SDA) U12.4(SDA)
SDATA: R24.2(N2) U4.10(SDATA) U10.10(SDATA) U11.10(SDATA) U12.10(SDATA)
UNNAMED_1_ADAU1761_I24_ADDR0: R5.2(N2) U5.3(ADDR0/CLATCH_N)
UNNAMED_1_ADAU1761_I24_ADDR1: R6.2(N2) U5.30(ADDR1/CDATA)
UNNAMED_1_ADAU1761_I24_CM: C20.1(N1) C21.2(N2) R15.2(N2) U5.7(CM)
UNNAMED_1_ADAU1761_I24_DVDDOUT: C16.1(N1) C17.1(N1) U5.24(DVDDOUT)
UNNAMED_1_ADAU1761_I24_LAUX: C22.2(N2) U5.6(LAUX)
UNNAMED_1_ADAU1761_I24_LHP: C26.2(N2) R16.1(N1) U5.20(LHP)
UNNAMED_1_ADAU1761_I24_LINN: R15.1(N1) U5.10(LINP) U5.11(LINN) U5.12(RINP) U5.13(RINN)
UNNAMED_1_ADAU1761_I24_MCLK: R10.2(N2) U5.2(MCLK)
UNNAMED_1_ADAU1761_I24_MONOOUT: R18.1(N1) U5.21(MONOOUT)
UNNAMED_1_ADAU1761_I24_RAUX: C24.2(N2) U5.14(RAUX)
UNNAMED_1_ADAU1761_I24_RHP: C27.2(N2) R17.1(N1) U5.19(RHP)
UNNAMED_1_CAP_I12_N1: C24.1(N1) C25.2(N2) R13.2(N2) R14.2(N2)
UNNAMED_1_CAP_I13_N2: C22.1(N1) C23.2(N2) R11.2(N2) R12.2(N2)
UNNAMED_1_CAP_I27_N2: C15.2(N2) L1.1(N1)
UNNAMED_1_CAP_I32_N1: C27.1(N1) J3.2(N2) P9.1(N1) R17.2(N2) R20.2(N2)
UNNAMED_1_CAP_I38_N1: C26.1(N1) J3.3(N3) P10.1(N1) R16.2(N2) R21.2(N2)
UNNAMED_1_CN2P_I1_N1: J2.3(N3) P8.1(N1) R13.1(N1)
UNNAMED_1_CN2P_I3_N1: J2.2(N2) P7.1(N1) R11.1(N1)
UNNAMED_1_CN3P_I48_N1: J3.1(N1) R18.2(N2) R19.2(N2)
UNNAMED_2_ADG3231_I6_Y: R23.1(N1) TP9.1(N1) U9.5(Y)
UNNAMED_2_ADG3231_I10_Y: R25.1(N1) TP7.1(N1) U7.5(Y)
UNNAMED_2_ADG3231_I12_Y: R24.1(N1) TP6.1(N1) U6.5(Y)
UNNAMED_2_ADG3231_I22_Y: R26.1(N1) TP8.1(N1) U8.5(Y)
UNNAMED_2_CN2P_I3_N2: P6.2(N2) R22.2(N2) Y1.1(3_STATE)
UNNAMED_2_CN2P_I8_N1: P11.1(N1) Y1.3(OUT)
UNNAMED_4_CAP4PV3_I13_IN: D3.C(N) F1.2(N2) FR1.1(IN)
UNNAMED_4_CAP4PV3_I13_OUT: D4.A(P) FR1.3(OUT)
UNNAMED_4_CAP_I6_N1: C3.1(N1) F1.1(N1) J1.3(SIG)
UNNAMED_4_DIOLED_I29_P: D2.A(P) R4.2(N2)
UNNAMED_4_DIOLED_I31_P: D1.A(P) R9.2(N2)
UNNAMED_5_CN8PA_I19_N7: P2.7(N7) P2.8(N8)
UNNAMED_5_CN120PV4_I18_EEPROMA0: P1.56(EEPROM_A0) R2.1(N1) U2.1(A0)
UNNAMED_5_CN120PV4_I18_SCL0: P1.79(SCL_0) U2.6(SCL)
UNNAMED_5_CN120PV4_I18_SDA0: P1.80(SDA_0) U2.5(SDA)
UNNAMED_5_IC24FC256_I14_A1: R1.2(N2) R3.1(N1) U2.2(A1)

Pads without a net: P1 2 5 7 8 9 10 12 13 14 15 16 18 19 20 21 22 24 25 26 27 29 30 31 32 33 34 35 37 38 39 45 47 48 49 50 51 53 54 55 57 59 60 61 62 64 65 66 67 68 70 71 72 73 74 76 82 83 84 85 87 88 89 90 91 92 94 95 96 97 99 100 101 102 103 105 106 107 108 110 111 112 113 114 116 119 120; P14 2 4 5 6 7 8 9; U1 4; U3 6; U5 5 15 16 17 18 27; U6 2; U7 2; U8 2; U9 2

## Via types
v1: diameter 0.635, hole 0.305, TOP to BOTTOM, 443 vias

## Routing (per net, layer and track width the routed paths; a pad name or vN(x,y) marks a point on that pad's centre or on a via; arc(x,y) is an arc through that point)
AVDD: length 37.2
  TOP w0.254: 22.11,52.07 TP5.1 ; TP5.1 24.88,52.07 ; TP5.1 23.5,50.68 ; TP5.1 23.5,53.46 ; 60.98,61.62 U5.23
  TOP w0.305: U5.8 67.41,64.62 69.47,66.67
  TOP w0.381: U7.1 v1(69.21,48.15) ; U6.1 v1(59.05,47.94) ; U8.1 v1(64.13,48.15)
  TOP w0.635: P6.1 91.9,59.86 Y1.4 88.39,58.55 88.16,58.32 C28.1 88.16,56.36 88.52,56.01 v1(88.77,56.01) ; 69.47,66.67 70.61,67.82 C14.2 71.92,68.92 71.88,68.96 L1.2 v1(70.87,69.72) ; 60.98,61.62 59.71,61.62 58.1,60.01 C13.2 ; C13.2 56.41,60.92 56.52,61.02 C12.2 ; C13.2 v1(56.41,58.42) ; U9.1 v1(79.01,60.65)
  vias: v1(25.65,52.45) v1(25.65,51.44) v1(25.65,50.42)
DGND: length 188.2
  TOP w0.254: 91.44,54.37 TP10.1 ; TP10.1 90.05,55.75 ; TP10.1 91.44,57.14 ; TP10.1 92.83,55.75 ; TP11.1 4.45,78.86 ; TP11.1 4.45,76.08 ; TP11.1 3.06,77.47 ; TP11.1 5.83,77.47 ; 21.51,24.39 C8.N ; C8.N 22.52,25.4 ; C8.N 21.51,26.41 ; C8.N 20.51,25.4 ; 1.79,20.96 TP1.1 ; TP1.1 3.17,22.34 ; TP1.1 3.17,19.57 ; TP1.1 4.56,20.96 ; 92.08,66.04 92.08,67.11 ; 92.08,66.04 92.08,64.97 ; 92.08,66.04 93.14,66.04 ; 92.08,66.04 91.01,66.04 ; 88.27,40.84 P9.2 ; P9.2 89.33,41.91 ; P9.2 88.27,42.98 ; P9.2 87.2,41.91 ; 87.2,66.04 88.27,66.04 ; 88.27,66.04 89.33,66.04 ; 88.27,66.04 88.27,64.97 ; 88.27,66.04 88.27,67.11 ; 89.42,78.74 TP12.1 ; TP12.1 90.81,80.13 ; TP12.1 92.19,78.74 ; TP12.1 90.81,77.35 ; P14.10 90.6,24.13 ; P14.10 88.47,24.13 ; P14.10 89.54,23.06 ; P14.10 89.54,25.2 ; J1.1 7.86,15.85 ; J1.1 9.95,13.77 ; J1.1 7.86,11.68 ; J1.1 5.78,13.77 ; P10.2 92.08,42.98 ; P10.2 92.08,40.84 ; P10.2 91.01,41.91 ; P10.2 93.14,41.91 ; P2.6 46.35,73.52 ; P2.6 47.49,72.39 ; P2.6 46.35,71.26 ; P2.6 45.22,72.39 ; 45.22,69.85 P2.5 ; P2.5 47.49,69.85 ; P2.5 46.35,70.98 ; P2.5 46.35,68.72 ; J1.2 11.11,11.05 ; J1.2 11.11,6.88 ; J1.2 13.2,8.97 ; J1.2 9.03,8.97 ; 90.81,11.95 TP2.1 ; TP2.1 90.81,14.72 ; TP2.1 89.42,13.33 ; TP2.1 92.19,13.33
  TOP w0.508: U1.2 v1(13.59,38.1)
  TOP w0.635: R19.1 v1(83.19,43.18) ; C21.1 74.49,65.79 v1(74.61,65.66) ; R21.1 v1(73.09,54.61) ; C7.2 v1(29.53,36.89) ; C33.2 v1(55.56,36.89) ; v1(76.71,62.74) 76.9,62.54 U9.4 ; C37.2 v1(42.54,36.89) ; R22.1 v1(82.55,64.26) ; C29.2 v1(67.69,36.89) ; R12.1 C23.1 ; U8.4 v1(62.23,45.8) ; C30.2 v1(69.91,36.89) ; C34.2 v1(57.78,36.89) ; C38.2 v1(44.77,36.89) ; R20.1 v1(73.09,43.5) ; C28.2 85.09,57.15 ; U7.4 v1(67.31,45.8) ; C2.2 v1(22.8,39.37) ; C9.2 v1(31.75,36.89) ; U6.4 v1(57.15,45.8) ; C1.2 v1(9.59,37.47)
  BOTTOM w0.254: TP10.1 92.95,55.75 ; TP10.1 91.44,54.24 ; TP10.1 91.44,57.27 ; TP10.1 89.93,55.75 ; TP11.1 4.45,78.98 ; TP11.1 2.93,77.47 ; TP11.1 5.96,77.47 ; TP11.1 4.45,75.96 ; J1.2 13.32,8.97 ; J1.2 11.11,11.18 ; J1.2 8.9,8.97 ; J1.2 11.11,6.75 ; TP1.1 4.69,20.96 ; TP1.1 1.66,20.96 ; TP1.1 3.17,22.47 ; TP1.1 3.17,19.44 ; 92.08,66.04 92.08,67.24 ; 92.08,66.04 90.88,66.04 ; 92.08,66.04 92.08,64.84 ; P9.2 89.46,41.91 ; P9.2 88.27,40.71 ; P9.2 87.07,41.91 ; P9.2 88.27,43.11 ; 5.65,13.77 J1.1 ; J1.1 7.86,11.55 ; J1.1 10.07,13.77 ; J1.1 7.86,15.98 ; 45.1,72.39 P2.6 ; P2.6 47.61,72.39 ; P2.6 46.35,73.65 ; P2.6 46.35,71.13 ; TP2.1 92.32,13.33 ; TP2.1 90.81,11.82 ; TP2.1 89.29,13.33 ; TP2.1 90.81,14.85 ; 89.29,78.74 TP12.1 ; TP12.1 92.32,78.74 ; TP12.1 90.81,77.23 ; TP12.1 90.81,80.25 ; 89.54,22.93 P14.10 ; P14.10 88.34,24.13 ; P14.10 90.73,24.13 ; P14.10 89.54,25.33 ; 88.27,66.04 88.27,67.24 ; 88.27,66.04 89.46,66.04 ; 88.27,66.04 88.27,64.84 ; 88.27,66.04 87.07,66.04 ; 46.35,68.59 P2.5 ; P2.5 46.35,71.11 ; P2.5 47.61,69.85 ; P2.5 45.1,69.85 ; C8.N 21.51,26.53 ; C8.N 21.51,24.27 ; C8.N 20.38,25.4 ; C8.N 22.64,25.4 ; 92.08,40.71 P10.2 ; P10.2 92.08,43.11 ; P10.2 90.88,41.91
  vias: v1(1.27,83.82) v1(1.27,80.01) v1(1.27,76.2) v1(1.27,72.39) v1(1.27,68.58) v1(1.27,64.77) v1(1.27,60.96) v1(1.27,57.15) v1(1.27,53.34) v1(1.27,49.53) v1(1.27,45.72) v1(1.27,41.91) v1(1.27,38.1) v1(1.27,34.29) v1(1.27,30.48) v1(1.27,26.67) v1(1.27,22.86) v1(1.27,19.05) v1(5.08,83.82) v1(5.08,46.99) v1(5.08,43.18) v1(5.08,39.37) v1(5.08,35.56) v1(5.08,31.75) v1(5.08,27.94) v1(5.08,22.86) v1(5.08,19.05) v1(8.89,87.63) v1(8.89,83.82) v1(8.89,80.01) v1(8.89,76.2) v1(8.89,72.39) v1(8.89,68.58) v1(8.89,64.77) v1(8.89,60.96) v1(8.89,57.15) v1(8.89,53.34) v1(8.89,49.53) v1(8.89,19.05) v1(12.7,91.44) v1(12.7,87.63) v1(12.7,83.82) v1(12.7,80.01) v1(12.7,34.29) v1(16.51,91.44) v1(16.51,87.63) v1(16.51,83.82) v1(16.51,80.01) v1(16.51,34.29) v1(16.51,30.48) v1(20.32,91.44) v1(20.32,87.63) v1(20.32,83.82) v1(20.32,80.01) v1(20.32,76.2) v1(20.32,72.39) v1(20.32,68.58) v1(20.32,64.77) v1(20.32,60.96) v1(20.32,57.15) v1(20.32,53.34) v1(20.32,30.48) v1(24.13,91.44) v1(24.13,87.63) v1(24.13,83.82) v1(24.13,80.01) v1(24.13,76.2) v1(24.13,72.39) v1(24.13,68.58) v1(24.13,64.77) v1(24.13,60.96) v1(24.13,57.15) v1(24.13,45.72) v1(24.13,41.91) v1(24.13,38.1) v1(24.13,34.29) v1(24.13,30.48) v1(24.13,26.67) v1(24.13,22.86) v1(27.56,30.1) v1(27.94,91.44) v1(27.94,87.63) v1(27.94,83.82) v1(27.94,80.01) v1(27.94,76.2) v1(27.94,72.39) v1(27.94,68.96) v1(27.94,26.67) v1(27.94,22.86) v1(27.94,19.05) v1(28.57,64.77) v1(28.57,60.96) v1(28.57,57.15) v1(28.57,53.34) v1(28.57,49.53) v1(28.57,45.72) v1(28.57,41.91) v1(28.57,38.1) v1(31.75,91.44) v1(31.75,87.63) v1(31.75,83.82) v1(31.75,80.01) v1(31.75,76.2) v1(31.75,72.64) v1(31.75,68.58) v1(31.75,64.77) v1(31.75,60.96) v1(31.75,57.15) v1(31.75,53.34) v1(31.75,49.53) v1(31.75,45.72) v1(31.75,41.91) v1(31.75,38.1) v1(31.75,11.43) v1(32.51,19.05) v1(32.51,15.24) v1(34.29,25.21) v1(35.24,29.53) v1(35.24,28.26) v1(35.24,25.21) v1(35.56,91.44) v1(35.56,87.63) v1(35.56,83.82) v1(35.56,80.01) v1(35.56,76.45) v1(35.56,72.39) v1(35.56,68.58) v1(35.56,64.77) v1(35.56,60.96) v1(35.56,57.15) v1(35.56,53.34) v1(35.56,49.53) v1(35.56,45.72) v1(35.56,41.91) v1(35.56,38.1) v1(35.56,19.18) v1(35.88,28.89) v1(35.88,25.84) v1(36.51,29.53) v1(36.51,28.26) v1(36.51,25.21) v1(37.46,25.21) v1(38.86,11.43) v1(39.37,80.01) v1(39.37,37.47) v1(39.37,15.24) v1(39.5,19.81) v1(41.91,55.25) v1(41.91,51.44) v1(41.91,47.62) v1(41.91,43.81) v1(41.91,37.47) v1(42.93,18.67) v1(43.18,83.19) v1(43.18,80.64) v1(43.18,41.91) v1(45.72,83.19) v1(45.72,59.05) v1(45.72,55.25) v1(45.72,51.44) v1(45.72,47.62) v1(45.72,43.81) v1(45.72,37.47) v1(46.99,87) v1(46.99,64.77) v1(46.99,41.91) v1(46.99,19.05) v1(46.99,11.43) v1(47.36,25.25) v1(48.26,29.53) v1(48.26,28.26) v1(48.26,25.21) v1(48.89,28.89) v1(48.89,25.84) v1(49.28,87.63) v1(49.53,79.38) v1(49.53,66.67) v1(49.53,59.05) v1(49.53,55.25) v1(49.53,51.44) v1(49.53,47.62) v1(49.53,43.81) v1(49.53,37.47) v1(49.53,29.53) v1(49.53,28.26) v1(49.53,25.21) v1(50.48,25.21) v1(50.8,19.05) v1(52.07,80.64) v1(53.34,66.67) v1(53.34,55.25) v1(54.61,87.63) v1(54.61,68.58) v1(54.61,64.77) v1(54.61,57.15) v1(54.61,19.05) v1(54.61,15.24) v1(57.15,55.25) v1(58.42,87.63) v1(58.42,80.01) v1(58.42,76.2) v1(58.42,72.39) v1(58.42,68.58) v1(58.42,53.34) v1(60.32,25.21) v1(61.28,29.53) v1(61.28,28.26) v1(61.28,25.21) v1(61.91,28.89) v1(61.91,25.84) v1(62.23,87.63) v1(62.23,80.01) v1(62.23,72.39) v1(62.23,19.05) v1(62.23,11.43) v1(62.55,29.53) v1(62.55,28.26) v1(62.55,25.21) v1(63.5,63.82) v1(63.5,62.87) v1(63.5,61.91) v1(63.5,25.21) v1(64.39,75.82) v1(64.45,63.82) v1(64.45,62.87) v1(64.45,61.91) v1(65.41,63.82) v1(65.41,62.87) v1(65.41,61.91) v1(66.04,87.63) v1(66.04,80.01) v1(66.04,53.34) v1(66.04,41.91) v1(66.8,77.22) v1(67.95,28.07) v1(69.85,87.63) v1(69.85,41.91) v1(69.85,15.24) v1(72.45,25.21) v1(72.52,87.88) v1(72.77,80.01) v1(73.41,29.46) v1(73.41,28.19) v1(73.41,25.21) v1(73.66,41.91) v1(74.04,28.83) v1(74.04,25.84) v1(74.68,29.46) v1(74.68,28.19) v1(74.68,25.21) v1(75.63,25.21) v1(77.47,57.15) v1(77.47,41.78) v1(77.47,38.1) v1(77.47,34.29) v1(77.47,19.05) v1(77.47,11.43) v1(77.72,89.03) v1(79.5,33.02) v1(81.28,87.63) v1(81.28,57.15) v1(81.28,41.78) v1(81.28,38.1) v1(81.28,26.67) v1(81.28,22.86) v1(81.28,19.05) v1(85.09,41.78) v1(85.09,38.1) v1(85.09,34.29) v1(85.09,26.67) v1(85.09,22.86) v1(85.09,19.05) v1(85.09,15.24) v1(85.34,87.63) v1(85.47,83.82) v1(88.9,80.01) v1(88.9,19.05) v1(88.9,15.24) v1(88.9,11.43) v1(92.71,80.01) v1(92.71,76.2) v1(92.71,57.15) v1(92.71,53.34) v1(92.71,38.1) v1(92.71,34.29) v1(92.71,30.48) v1(92.71,26.67) v1(92.71,22.86) v1(92.71,19.05) v1(92.71,15.24) v1(92.71,11.43)
VIN: length 23.5
  TOP w0.254: TP4.1 10.28,33.02 ; TP4.1 8.89,31.63 ; TP4.1 7.5,33.02 ; TP4.1 8.89,34.41 ; C8.P 16.51,26.41 ; C8.P 15.5,25.4 ; C8.P 17.52,25.4 ; C8.P 16.51,24.39
  TOP w0.356: 41.27,82.55 47.73,89 P1.1
  TOP w0.635: C10.2 v1(34.61,21.34) ; C35.2 v1(60.64,21.34) ; C39.2 v1(47.62,21.34)
  vias: v1(11.56,31.62) v1(11.56,30.61) v1(12.7,31.62) v1(12.7,30.61) v1(32.89,26.04) v1(32.89,24.77) v1(32.89,23.5) v1(32.89,22.23) v1(33.97,26.35) v1(37.78,26.35) v1(38.86,26.04) v1(38.86,24.77) v1(38.86,23.5) v1(38.86,22.23) v1(45.85,26.1) v1(45.85,24.83) v1(45.91,23.49) v1(45.91,22.23) v1(46.99,26.35) v1(50.8,26.35) v1(51.88,26.04) v1(51.88,24.77) v1(51.88,23.5) v1(51.88,22.23) v1(58.93,26.04) v1(58.93,24.77) v1(58.93,23.5) v1(58.93,22.23) v1(60.01,26.35) v1(63.82,26.35) v1(64.9,26.04) v1(64.9,24.77) v1(64.9,23.5) v1(64.9,22.23) v1(71.06,26.04) v1(71.06,24.77) v1(71.06,23.5) v1(71.06,22.23) v1(72.14,26.35) v1(75.95,26.35) v1(77.03,26.04) v1(77.03,24.77) v1(77.03,23.5) v1(77.03,22.23)
ADC_SDATA: length 15.5
  TOP w0.254: 63.2,59.39 U5.26
  TOP w0.381: U6.3 57.15,50.49 59.05,52.39 61.91,52.39 63.2,53.68 63.2,59.39
ADDR_1: length 128.8
  TOP w0.305: U10.3 77.03,28.89 77.34,29.21 v1(78.87,29.21) ; v1(72.9,92.33) 72.93,92.3 P1.43
  BOTTOM w0.381: v1(72.9,92.33) 56.13,92.33 P18.1 36.58,72.77 36.58,42.8 40,39.37 59.56,39.37 60.58,38.35 72.26,38.35 79.5,31.12 79.5,29.85 v1(78.87,29.21)
ADDR_2: length 113.3
  TOP w0.305: 66.8,29.39 65.39,29.39 64.9,28.89 U11.3 ; v1(73.15,83.06) 72.93,83.28 P1.78
  TOP w0.381: 66.8,29.39 66.98,29.39 67.25,29.66 67.25,30.41 64.77,32.89 64.77,37.06 65.53,37.82 v1(65.53,39.62)
  BOTTOM w0.381: v1(73.15,83.06) 49.4,83.06 P18.2 38.61,72.26 38.61,43.94 41.91,40.64 64.52,40.64 v1(65.53,39.62)
ADDR_3: length 102.8
  TOP w0.305: 53.34,29.39 52.38,29.39 51.88,28.89 U12.3 ; P1.44 73.53,89.54 v1(73.66,89.41)
  TOP w0.381: P18.3 51.56,72.26 51.56,54.74 53.09,53.21 53.09,32.77 54.36,31.5 54.36,29.85 53.9,29.39 53.34,29.39
  BOTTOM w0.381: P18.3 53.21,70.61 65.02,70.61 76.71,82.3 76.71,86.36 v1(73.66,89.41)
ADDR_4: length 95.3
  TOP w0.305: v1(73.91,82.3) 73.91,83.44 73.53,83.83 P1.77 ; 40.26,29.39 39.36,29.39 38.86,28.89 U4.3
  TOP w0.381: 40.26,29.39 40.69,29.39 41.15,29.85 41.15,30.48 37.97,33.66 37.97,77.34 40.13,79.5 46.86,79.5 P18.4
  BOTTOM w0.381: v1(73.91,82.3) 55.75,82.3 50.93,77.47 P18.4
BCLK: length 55.6
  TOP w0.254: 74.54,31.55 U10.7 ; 62.41,31.55 U11.7 ; 36.38,31.55 U4.7 ; 49.4,31.55 U12.7
  TOP w0.381: v1(36.38,33.97) 36.38,31.55 ; v1(74.54,33.97) 74.54,31.55 ; R26.2 63.5,35.06 v1(62.41,33.97) 62.41,31.55 ; v1(49.4,33.97) 49.4,31.55
  BOTTOM w0.381: v1(74.54,33.97) v1(62.41,33.97) v1(49.4,33.97) v1(36.38,33.97)
BCLK_0: length 12.1
  TOP w0.254: U5.28 64.2,58.61 64.14,58.55 64.14,58.48
  TOP w0.381: 64.14,58.48 64.14,53.35 62.23,51.44 U8.3
IOVDD: length 22.4
  TOP w0.254: 67.85,60.87 67.6,61.11 U5.1
  TOP w0.33: U2.3 v1(69.78,77.16) ; U2.8 v1(61.13,75.86)
  TOP w0.381: U7.6 v1(69.21,45.72) ; U6.6 v1(59.05,45.72) ; U8.6 v1(64.13,45.72)
  TOP w0.635: U9.6 v1(76.58,60.65) ; R1.1 v1(63.37,73.66) ; 67.85,60.87 67.95,60.77 C19.1 68.86,57.37 68.96,57.47 C18.1 v1(71.44,57.47)
  TOP w0.762: 22.48,35.56 TP3.1 ; TP3.1 20.96,34.17 ; TP3.1 19.3,35.56 ; TP3.1 20.96,37.21
  vias: v1(23.24,37.47) v1(23.24,36.45) v1(23.24,35.43) v1(29.85,33.02) v1(30.8,33.02) v1(31.75,33.02) v1(42.86,33.02) v1(43.81,33.02) v1(44.77,33.02) v1(55.88,33.02) v1(56.83,33.02) v1(57.78,33.02) v1(68.01,33.02) v1(68.96,33.02) v1(69.91,33.02) v1(81.03,33.02) v1(81.92,33.02) v1(82.8,33.02)
LRCLK: length 62.2
  TOP w0.254: 48.39,31.55 U12.9 ; 61.41,31.55 U11.9 ; 35.38,31.55 U4.9 ; 73.54,31.55 U10.9
  TOP w0.381: 73.54,31.55 v1(73.54,34.93) 73.54,36.44 71.72,38.27 R25.2 ; v1(48.39,34.93) 48.39,31.55 ; v1(61.41,34.93) 61.41,31.55 ; v1(35.38,34.93) 35.38,31.55
  BOTTOM w0.381: v1(35.38,34.93) v1(48.39,34.93) v1(61.41,34.93) v1(73.54,34.93)
LRCLK_0: length 12.4
  TOP w0.254: U5.29 64.7,58.61 64.76,58.55 64.76,58.48
  TOP w0.381: U7.3 67.31,50.8 64.77,53.34 64.77,53.97 64.76,53.98 64.76,58.48
MCLK: length 78
  TOP w0.254: v1(75.44,32.07) 75.04,31.68 U10.6 ; v1(37.15,32.07) 36.88,31.8 U4.6 ; v1(63.5,32.07) 62.91,31.49 U11.6 ; v1(50.48,32.07) 49.9,31.49 U12.6
  TOP w0.381: R23.2 R10.1 71.97,60.36 72.26,60.07 72.26,58.55 73.03,57.79 73.03,56.01 72.26,55.25 72.26,39.18 75.44,36 v1(75.44,32.07)
  BOTTOM w0.381: v1(75.44,32.07) v1(63.5,32.07) v1(50.48,32.07) 37.15,32.07 v1(37.15,32.07)
MCLK_0: length 2.9
  TOP w0.381: P11.2 81.6,62.54 U9.3
OUTL+_1: length 20.2
  TOP w0.305: U10.1 77.09,27.89 77.29,27.69 77.72,27.69
  TOP w0.508: P3.1 81.03,12.95 79.88,12.95 78.99,13.84 78.99,26.92 78.23,27.69 77.72,27.69
OUTL+_2: length 21
  TOP w0.305: 65.41,27.69 64.9,27.69 64.69,27.89 U11.1
  TOP w0.508: P4.1 65.79,12.95 64.64,12.95 63.75,13.84 63.75,16.95 66.42,19.62 66.42,27.18 65.91,27.69 65.41,27.69
OUTL+_3: length 22.5
  TOP w0.305: U12.1 52.12,27.89 52.32,27.69 52.7,27.69
  TOP w0.508: 52.7,27.69 53.21,27.69 53.85,27.05 53.85,20.89 48.51,15.56 48.51,13.84 49.4,12.95 50.55,12.95 P12.1
OUTL+_4: length 25.9
  TOP w0.305: U4.1 38.86,27.89 39.07,27.69 39.62,27.69
  TOP w0.508: 39.62,27.69 40.13,27.69 40.89,26.92 40.89,19.62 39.43,18.16 35.12,18.16 33.27,16.32 33.27,13.84 34.16,12.95 35.31,12.95 P16.1
OUTL-_1: length 20.1
  TOP w0.305: U10.2 77.29,28.39 77.34,28.45 77.72,28.45
  TOP w0.508: P3.2 81.03,13.72 80.2,13.72 79.76,14.16 79.76,27.24 78.55,28.45 77.72,28.45
OUTL-_2: length 20.9
  TOP w0.305: 65.41,28.45 65.35,28.39 U11.2
  TOP w0.508: 65.41,28.45 66.23,28.45 67.18,27.5 67.18,19.3 64.52,16.64 64.52,14.16 64.96,13.72 65.79,13.72 P4.2
OUTL-_3: length 22.4
  TOP w0.305: 52.7,28.45 52.32,28.45 52.27,28.39 U12.2
  TOP w0.508: 52.7,28.45 53.53,28.45 54.61,27.37 54.61,20.57 49.28,15.24 49.28,14.16 49.72,13.72 50.55,13.72 P12.2
OUTL-_4: length 25.9
  TOP w0.305: 39.62,28.45 39.24,28.45 39.19,28.39 U4.2
  TOP w0.508: 39.62,28.45 40.45,28.45 41.66,27.24 41.66,19.3 39.75,17.4 35.43,17.4 34.04,16 34.04,14.16 34.48,13.72 35.31,13.72 P16.2
OUTR+_1: length 25.4
  TOP w0.305: 70.87,27.81 71.42,27.81 71.5,27.89 U10.15
  TOP w0.508: P13.1 75.18,12.95 76.33,12.95 77.22,13.84 77.22,16.83 74.99,19.05 71.18,19.05 69.47,20.76 69.47,27.18 70.1,27.81 70.87,27.81
OUTR+_2: length 22.1
  TOP w0.305: U11.15 59.31,27.89 59.1,27.69 58.67,27.69
  TOP w0.508: P5.1 59.94,12.95 61.09,12.95 61.98,13.84 61.98,16.19 57.15,21.02 57.15,27.05 57.78,27.69 58.67,27.69
OUTR+_3: length 21.2
  TOP w0.305: 45.59,27.69 46.15,27.69 46.35,27.89 U12.15
  TOP w0.508: P15.1 44.7,12.95 45.85,12.95 46.74,13.84 46.74,17.59 44.07,20.26 44.07,27.05 44.7,27.69 45.59,27.69
OUTR+_4: length 19.8
  TOP w0.305: 32.77,27.81 33.32,27.81 33.4,27.89 U4.15
  TOP w0.508: P17.1 29.46,12.95 30.61,12.95 31.5,13.84 31.5,27.18 32.13,27.81 32.77,27.81
OUTR-_1: length 25.4
  TOP w0.305: 70.87,28.58 71.32,28.58 71.5,28.39 U10.14
  TOP w0.508: 70.87,28.58 69.79,28.58 68.71,27.5 68.71,20.45 70.87,18.29 74.68,18.29 76.45,16.51 76.45,14.16 76.01,13.72 75.18,13.72 P13.2
OUTR-_2: length 22
  TOP w0.305: 58.67,28.45 59.25,28.45 59.31,28.39 U11.14
  TOP w0.508: 58.67,28.45 57.47,28.45 56.39,27.37 56.39,20.7 61.21,15.88 61.21,14.16 60.77,13.72 59.94,13.72 P5.2
OUTR-_3: length 21.2
  TOP w0.305: U12.14 46.35,28.39 46.3,28.45 45.59,28.45
  TOP w0.508: 45.59,28.45 44.39,28.45 43.31,27.37 43.31,19.94 45.97,17.27 45.97,14.16 45.53,13.72 44.7,13.72 P15.2
OUTR-_4: length 19.8
  TOP w0.305: U4.14 33.4,28.39 33.22,28.58 32.77,28.58
  TOP w0.508: P17.2 29.46,13.72 30.29,13.72 30.73,14.16 30.73,27.5 31.81,28.58 32.77,28.58
SCL: length 188.4
  TOP w0.254: v1(66.67,59.05) 66.67,59.65 66.2,60.12 U5.32
  TOP w0.305: v1(65.47,30.73) 65.09,30.73 64.25,29.89 U11.5 ; P1.42 72.33,89.21 73.41,88.14 v1(80.14,88.14) ; U4.5 38.21,29.89 39.05,30.73 v1(39.43,30.73) ; v1(77.6,30.73) 77.34,30.73 76.5,29.89 U10.5 ; U12.5 51.23,29.89 52.07,30.73 v1(52.45,30.73)
  TOP w0.381: P14.1 85.51,35.78 R7.2 80.23,35.78 77.6,33.15 v1(77.6,30.73) ; v1(52.45,30.73) 52.45,31.37 50.8,33.02 v1(50.8,48.26) 41.27,57.79 TP13.1 P2.1 P2.2
  BOTTOM w0.381: v1(39.43,30.73) 39.81,31.12 52.07,31.12 v1(52.45,30.73) 52.83,31.12 65.09,31.12 v1(65.47,30.73) 65.85,31.12 77.22,31.12 v1(77.6,30.73) ; v1(50.8,48.26) 57.78,48.26 66.67,57.15 v1(66.67,59.05) 66.55,59.18 60.07,59.18 58.67,60.58 58.67,65.15 60.71,67.18 66.55,67.18 80.14,80.77 v1(80.14,88.14)
SDA: length 185.5
  TOP w0.254: U5.31 65.7,59.68 65.95,59.43 v1(65.95,58.42)
  TOP w0.305: v1(66.36,30.16) 66.17,29.97 65.09,29.97 64.51,29.39 U11.4 ; v1(53.34,30.16) 53.15,29.97 52.07,29.97 51.49,29.39 U12.4 ; v1(78.49,30.16) 78.3,29.97 77.34,29.97 76.76,29.39 U10.4 ; U4.4 38.47,29.39 39.05,29.97 40.13,29.97 v1(40.32,30.16) ; P1.41 71.73,87.66 72.39,87 73.38,87 73.39,86.98 73.93,86.98 73.94,87 v1(78.99,87)
  TOP w0.381: P2.4 P2.3 TP14.1 43.81,59.44 v1(51.82,51.44) 51.82,33.02 53.34,31.5 v1(53.34,30.16) ; P14.3 85.51,30.26 R8.2 78.59,30.26 v1(78.49,30.16)
  BOTTOM w0.381: v1(78.99,87) 78.99,81.28 66.04,68.33 59.18,68.33 57.4,66.55 57.4,60.07 59.05,58.42 v1(65.95,58.42) 58.96,51.44 v1(51.82,51.44) ; v1(40.32,30.16) 40.64,30.48 51.43,30.48 52.07,29.85 53.02,29.85 v1(53.34,30.16) 53.66,30.48 64.52,30.48 65.15,29.85 66.04,29.85 v1(66.36,30.16) 66.67,30.48 75.82,30.48 76.45,29.85 78.17,29.85 v1(78.49,30.16)
SDATA: length 63
  TOP w0.254: 47.69,31.69 47.89,31.48 U12.10 ; 34.67,31.69 34.88,31.48 U4.10 ; U11.10 60.91,31.48 60.71,31.69 ; U10.10 73.04,31.48 72.83,31.69
  TOP w0.381: R24.2 58.17,37.59 59.88,35.88 v1(60.32,35.88) 60.32,32.07 60.71,31.69 ; v1(34.29,35.88) 34.29,32.07 34.67,31.69 ; 47.69,31.69 47.31,32.07 v1(47.31,35.88) ; v1(72.45,35.88) 72.45,32.07 72.83,31.69
  BOTTOM w0.381: v1(72.45,35.88) v1(60.32,35.88) v1(47.31,35.88) v1(34.29,35.88)
UNNAMED_1_ADAU1761_I24_ADDR0: length 4
  TOP w0.305: R5.2 69.34,63.75 67.7,62.12 U5.3
UNNAMED_1_ADAU1761_I24_ADDR1: length 4
  TOP w0.305: U5.30 65.2,59.18 65.29,59.1 65.29,57.36 R6.2
UNNAMED_1_ADAU1761_I24_CM: length 21.4
  TOP w0.305: U5.7 67.92,64.11 68.26,64.45
  TOP w0.381: R15.2 v1(67.53,66.46) ; 68.26,64.45 69.6,65.79 C21.2 71.92,66.42 72.3,66.8 75.44,66.8 v1(75.82,66.42) 75.88,66.36 C20.1
  BOTTOM w0.381: v1(67.53,66.46) 75.78,66.46 v1(75.82,66.42)
UNNAMED_1_ADAU1761_I24_DVDDOUT: length 6.6
  TOP w0.305: U5.24 61.5,61.11 61.28,60.9
  TOP w0.381: C16.1 60.49,57.79 60.59,57.68 C17.1 61.59,58.48 61.02,59.05 61.02,60.64 61.28,60.9
UNNAMED_1_ADAU1761_I24_LAUX: length 15
  TOP w0.305: U5.6 68.31,63.61 68.77,64.07
  TOP w0.457: 68.77,64.07 69.47,64.77 73.28,64.77 74.42,63.63 78.61,63.63 79.44,64.45 C22.2
UNNAMED_1_ADAU1761_I24_LHP: length 27.6
  TOP w0.254: v1(59.98,63.45) 60.32,63.11 U5.20
  TOP w0.635: v1(73.03,50.16) R16.1 C26.2
  BOTTOM w0.635: v1(73.03,50.16) 68.83,54.36 68.83,59.56 67.44,60.96 62.36,60.96 61.34,61.98 61.34,62.87 60.75,63.45 v1(59.98,63.45)
UNNAMED_1_ADAU1761_I24_LINN: length 3.9
  TOP w0.254: U5.13 U5.12 U5.11 U5.10 65.7,66.02
  TOP w0.381: R15.1 65.7,67.51 65.7,66.02
UNNAMED_1_ADAU1761_I24_MCLK: length 3.4
  TOP w0.254: U5.2 68.07,61.62
  TOP w0.381: R10.2 70.16,61.62 68.07,61.62
UNNAMED_1_ADAU1761_I24_MONOOUT: length 42
  TOP w0.254: U5.21 60.46,62.62 v1(60.32,62.48)
  TOP w0.635: R18.1 v1(85.41,43.18)
  BOTTOM w0.635: v1(60.32,62.48) 60.32,60.83 61.21,59.94 67.18,59.94 67.82,59.31 67.82,51.05 74.8,44.07 84.52,44.07 v1(85.41,43.18)
UNNAMED_1_ADAU1761_I24_RAUX: length 23.2
  TOP w0.254: U5.14 63.7,66.21
  TOP w0.635: 63.7,66.21 63.7,68.78 66.93,72.01 72.14,72.01 74.68,74.55 74.68,79.25 75.12,79.69 C24.2
UNNAMED_1_ADAU1761_I24_RHP: length 34.4
  TOP w0.254: U5.19 61.1,63.61 v1(60.45,64.26)
  TOP w0.635: C27.2 R17.1 v1(73.03,47.94)
  BOTTOM w0.635: v1(60.45,64.26) 61.09,64.9 68.58,64.9 70.48,62.99 70.48,55.75 74.93,51.31 74.93,48.9 73.98,47.94 v1(73.03,47.94)
UNNAMED_1_CAP_I12_N1: length 6.7
  TOP w0.635: C24.1 76.3,77.89 R14.2 C25.2 81.15,77.25 R13.2
UNNAMED_1_CAP_I13_N2: length 8.2
  TOP w0.635: C23.2 R12.2 78.74,67.06 79.44,66.36 C22.1 81.92,66.36 82.02,66.46 R11.2
UNNAMED_1_CAP_I27_N2: length 2.2
  TOP w0.381: C15.2 72.99,71.46 72.52,70.99 L1.1
UNNAMED_1_CAP_I32_N1: length 23.2
  TOP w0.635: P9.1 88.27,47.5 87.25,48.51 78.36,48.51 v1(77.22,47.37) 76.64,47.94 R17.2 C27.1 R20.2
  BOTTOM w0.635: J3.2 77.26,47.42 v1(77.22,47.37)
UNNAMED_1_CAP_I38_N1: length 30.9
  TOP w0.635: P10.1 92.08,50.67 87.88,54.86 v1(84.58,54.86) 84.33,54.61 R21.2 C26.1 R16.2
  BOTTOM w0.635: v1(84.58,54.86) 84.63,54.82 J3.3
UNNAMED_1_CN2P_I1_N1: length 20.4
  TOP w0.635: P8.1 92.08,74.55 87.38,79.25 v1(84.07,79.25) 83.78,78.96 R13.1
  BOTTOM w0.635: J2.3 84.38,78.95 v1(84.07,79.25)
UNNAMED_1_CN2P_I3_N1: length 11.4
  TOP w0.635: v1(83.06,69.47) R11.1 87.85,68.16 P7.1
  BOTTOM w0.635: v1(83.06,69.47) 83.06,69.72 81.23,71.55 J2.2
UNNAMED_1_CN3P_I48_N1: length 6.5
  TOP w0.635: v1(86.74,47.5) 85.87,47.5 85.41,47.07 R18.2 R19.2
  BOTTOM w0.635: J3.1 86.86,47.42 v1(86.74,47.5)
UNNAMED_2_ADG3231_I6_Y: length 5.5
  TOP w0.381: U9.5 76.9,61.59 76.77,61.72 R23.1 75.78,59.27 TP9.1
UNNAMED_2_ADG3231_I10_Y: length 6.8
  TOP w0.381: U7.5 TP7.1 68.33,43.12 R25.1
UNNAMED_2_ADG3231_I12_Y: length 6.8
  TOP w0.381: R24.1 58.17,43.18 TP6.1 U6.5
UNNAMED_2_ADG3231_I22_Y: length 6.9
  TOP w0.381: U8.5 TP8.1 63.5,42.86 R26.1
UNNAMED_2_CN2P_I3_N2: length 8.4
  TOP w0.381: P6.2 91.9,62.06 Y1.1 88.39,63.12 87.25,64.26 R22.2
UNNAMED_2_CN2P_I8_N1: length 3.6
  TOP w0.381: P11.1 83.36,59.86 Y1.3
UNNAMED_4_CAP_I6_N1: length 6
  TOP w1.27: 16.13,15.79 J1.3 16.32,11.56
UNNAMED_4_DIOLED_I29_P: length 2.6
  TOP w1.016: R4.2 D2.A
UNNAMED_4_DIOLED_I31_P: length 2.6
  TOP w1.016: R9.2 D1.A
UNNAMED_5_CN8PA_I19_N7: length 2.5
  TOP w0.381: P2.8 P2.7
UNNAMED_5_CN120PV4_I18_EEPROMA0: length 29.8
  TOP w0.305: P1.56 80.73,89.83 81.53,89.03 83.31,89.03 84.58,87.76 84.58,83.82 83.31,82.55 76.33,82.55 70.9,77.13 R2.1 70.06,76.2 69.72,75.86 U2.1
UNNAMED_5_CN120PV4_I18_SCL0: length 14
  TOP w0.305: U2.6 65.73,77.16 72.33,83.76 P1.79
UNNAMED_5_CN120PV4_I18_SDA0: length 12.9
  TOP w0.305: P1.80 71.73,84.08 65.46,77.81 U2.5
UNNAMED_5_IC24FC256_I14_A1: length 6.7
  TOP w0.305: U2.2 66.86,76.51 66.26,75.91 R1.2 R3.1

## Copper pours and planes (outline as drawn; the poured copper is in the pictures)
AVDD on TOP: 19.18,49.4 21.34,49.4 21.72,49.78 21.72,53.21 22.48,53.98 25.15,53.98 26.04,53.09 26.04,50.04 25.27,49.28 23.37,49.28 23.11,49.02 23.11,45.09 21.97,45.09 21.97,47.12 21.34,47.75 19.18,47.75
AVDD on L3_PWR: 20.32,47.62 36.83,47.62 36.83,63.5 54.61,63.5 54.61,46.99 89.54,46.99 89.54,57.15 85.09,61.59 78.11,61.59 78.11,55.25 69.22,55.25 69.22,63.5 71.76,66.04 71.76,70.48 20.32,70.48 ; 1 cut-out
DGND on TOP: 8.89,0.65 8.89,6.35 0.65,6.35 0.65,85.09 6.99,85.09 6.99,90.81 8.89,90.81 8.89,93.33 93.33,93.33 93.33,6.35 85.09,6.35 85.09,0.65 ; 7 cut-outs
DGND on BOTTOM: 8.89,0.65 8.89,6.35 0.65,6.35 0.65,85.09 6.99,85.09 6.99,90.81 8.89,90.81 8.89,93.33 93.33,93.33 93.33,6.35 85.09,6.35 85.09,0.65 ; 3 cut-outs
DGND on L2_DGND: 0.65,0.65 0.65,93.33 93.33,93.33 93.33,0.65
VIN on TOP: 34.92,27.3 33.97,27.3 33.97,26.67 32.51,26.67 32.51,21.27 39.37,21.27 39.37,26.67 37.78,26.67 37.78,27.3 36.83,27.3 36.83,26.04 38.42,26.04 38.42,22.86 33.34,22.86 33.34,26.04 34.92,26.04
VIN on TOP: 3.17,61.47 24.64,82.93 41.02,82.93 47.62,89.53 47.88,89.53 48.01,89.41 48.01,88.9 40,80.9 32.51,80.9 16.38,64.77 16.38,49.66 14.48,49.66 14.48,48.77 16.38,48.77 16.38,47.75 12.7,47.75 12.45,48.01 12.45,49.78 12.07,50.16 9.78,50.16 8.89,49.28 8.89,42.93 12.45,39.37 15.75,39.37 15.75,38.73 12.95,38.73 12.95,37.47 15.75,37.47 15.75,36.83 11.81,36.83 11.81,38.23 11.56,38.48 9.4,38.48 8.76,37.85 8.76,36.2 11.3,33.66 14.22,33.66 14.22,30.23 24.77,19.69 24.77,17.02 16.64,17.02 3.17,30.48
VIN on TOP: 60.96,27.3 60.01,27.3 60.01,26.67 58.42,26.67 58.42,21.27 65.41,21.27 65.41,26.67 63.82,26.67 63.82,27.3 62.86,27.3 62.86,26.04 64.45,26.04 64.45,22.86 59.37,22.86 59.37,26.04 60.96,26.04
VIN on TOP: 47.94,27.3 46.99,27.3 46.99,26.67 45.4,26.67 45.4,21.27 52.39,21.27 52.39,26.67 50.8,26.67 50.8,27.3 49.85,27.3 49.85,26.04 51.43,26.04 51.43,22.86 46.35,22.86 46.35,26.04 47.94,26.04
VIN on TOP: 73.09,27.3 72.14,27.3 72.14,26.67 70.55,26.67 70.55,21.27 77.53,21.27 77.53,26.67 75.95,26.67 75.95,27.3 74.99,27.3 74.99,26.04 76.58,26.04 76.58,22.86 71.5,22.86 71.5,26.04 73.09,26.04
VIN on L3_PWR: 6.35,0.64 6.35,6.35 1.27,6.35 1.27,33.02 17.14,33.02 17.14,27.94 92.71,27.94 92.71,6.35 87.63,6.35 87.63,0.64
IOVDD on TOP: 34.29,29.53 34.29,28.7 31.88,28.7 28.96,31.62 28.96,31.69 28.89,31.75 28.89,34.61 32.38,34.61 32.38,30.48 33.34,29.53
IOVDD on TOP: 67.06,34.61 70.55,34.61 70.55,30.48 71.5,29.53 72.45,29.53 72.52,29.46 72.52,28.7 70.99,28.7 67.06,32.64
IOVDD on TOP: 16.64,38.73 18.41,38.73 18.67,38.48 18.67,34.8 19.81,33.66 22.61,33.66 23.62,34.67 23.62,37.59 22.86,38.35 20.83,38.35 20.57,38.61 20.57,42.55 19.43,42.55 19.43,40.51 18.29,39.37 16.64,39.37
IOVDD on TOP: 80.65,34.54 80.65,31.5 83.19,31.5 83.19,34.54
IOVDD on TOP: 41.91,31.75 41.91,34.61 45.4,34.61 45.4,30.48 46.35,29.53 47.31,29.53 47.31,29.46 47.37,29.46 47.37,28.7 44.96,28.7
IOVDD on TOP: 54.99,34.61 58.42,34.61 58.42,30.48 59.37,29.53 60.32,29.53 60.32,28.7 58.8,28.7 54.99,32.51
